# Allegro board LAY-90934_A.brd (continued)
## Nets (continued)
GND: BH1.1 BH2.1 BH3.1 BH4.1 BH5.1 BT1.3 C1.2 C2.2 C3.2 C4.2 C5.2 C6.2 C7.2 C8.2 C9.2 C10.2 C11.2 C12.2 C13.2 C14.2 C15.2 C16.2 C17.2 C18.2 C19.2 C20.2 C21.2 C23.2 C24.2 C25.2 C26.2 C27.1 C28.2 C29.2 C30.2 C31.2 C32.2 C33.2 C34.2 C35.2 C36.2 C37.2 C38.2 C39.2 C40.2 C41.2 C42.2 C43.2 C44.2 C45.2 C46.2 C47.2 C48.2 C49.2 C50.2 C52.2 C54.2 C58.2 C61.2 C63.2 C64.2 C65.2 C66.2 C67.2 C69.2 C70.2 C71.2 C73.2 C74.2 C75.2 C76.2 C77.2 C78.2 C80.2 C81.2 C82.2 C83.2 C84.2 C86.2 C87.1 C88.2 C89.2 C90.2 C91.2 C92.2 C93.2 C94.2 C95.2 C96.2 C97.2 C98.2 C99.2 C100.2 C101.2 C102.2 C103.2 C104.2 C105.2 C106.2 C107.2 C108.2 C109.2 C110.2 C111.2 C112.2 C113.2 C114.2 C115.2 C116.2 C117.2 C118.2 C119.2 C120.2 C121.2 C124.2 C125.1 C127.2 C128.2 C129.2 C130.2 C131.2 C132.2 C133.2 C134.2 C135.2 C136.2 C137.2 C138.2 C139.2 C140.2 C141.2 C142.2 C143.2 C144.2 C145.2 C146.2 C148.2 C150.2 C151.2 C152.2 C153.2 C154.2 C155.2 C156.2 C157.1 C158.2 C159.2 C160.2 C161.2 C162.2 C163.2 C164.2 C167.2 C169.1 C170.2 C171.2 C172.1 C174.1 C175.2 C176.2 C177.2 C178.2 C179.2 C180.2 C182.2 C183.2 C184.2 C185.2 C186.2 C187.1 C188.2 C189.2 C190.2 C191.2 C192.1 C193.2 C194.2 C195.2 C196.2 C197.2 C198.2 C199.2 C200.2 C201.2 C202.2 C203.2 C204.2 C205.2 C206.2 C207.2 C208.2 C209.2 C210.2 C211.2 C212.2 C213.2 C214.2 C215.2 C216.2 C217.2 C218.2 C219.2 C220.2 C221.2 C222.2 C223.2 C224.2 C225.2 C226.2 C227.2 C228.2 C229.2 C230.2 C231.2 C232.2 C233.2 C234.2 C235.2 C236.2 C237.2 C238.2 C239.1 C240.2 C241.1 C242.1 C243.2 C244.2 C245.2 C246.1 C247.2 C248.1 C249.2 C250.2 C251.2 C252.2 C253.2 C255.2 C256.2 C257.2 C258.2 C259.2 C260.2 C261.2 C262.2 C263.2 C264.2 C266.2 C267.2 C268.2 C269.2 C271.2 C272.2 C273.2 C275.2 C276.2 C277.2 C278.2 C279.2 C280.2 C281.2 C282.2 C284.2 C285.2 C286.2 C287.2 C288.2 C289.2 C290.2 C291.2 C292.2 C293.2 C294.2 C295.2 C296.2 C297.2 C298.2 C299.2 C300.2 C301.2 C302.2 C303.2 C304.2 C305.2 C307.2 C308.2 C309.2 C310.2 C311.2 C312.1 C313.2 C314.2 C315.2 C316.2 C317.2 C318.2 D2.3(COM_CATHODE) D6.2(C2) D7.2(C2) D9.2(C2) D10.2(A2) D11.2(C2) D12.2(C2) D13.2(C2) D14.2(A2) D28.C(CATHODE) D29.A GND1.1(TP) GND2.1(TP) GND3.1(PIN1) GND4.1(PIN1) GND5.1(PIN1) GND6.1(PIN1) GND7.1(TP) GND8.1(PIN1) GND9.1(PIN1) GND10.1(PIN1) GND11.1(PIN1) GND12.1(PIN1) GND13.1(PIN1) GND14.1(PIN1) GND15.1(PIN1) GND16.1(PIN1) GND17.1(TP) GND18.1(PIN1) GND19.1(PIN1) GND20.1(PIN1) GND21.1(PIN1) GND22.1(PIN1) GND23.1(PIN1) GND24.1(PIN1) GND25.1(PIN1) GND26.1(TP) GND27.1(TP) GND28.1(PIN1) J1.5 J1.6(B3) J2.4 J3.7 J3.8(B4) J4.6 J4.9 J4.14 J4.20 J4.25 J4.30 J4.34 J4.39 J6.6(VSS) J6.10 J6.11 J6.12 J6.13 J7.3 J7.5 J8.1 J8.7 J8.18 J8.33 J8.39 J8.45 J8.51 J8.57 J8.63 J8.69 J8.75 J10.2 J11.A1 J11.A12 J11.B1 J11.B12 J11.SH1 J11.SH2 J11.SH3 J11.SH4 J12.A1 J12.A12 J12.B1 J12.B12 J12.SH1 J12.SH2 J12.SH3 J12.SH4 J13.A12 J13.B12 J13.SH1 J13.SH2 J13.SH3 J13.SH4 Q1.2(SOURCE) Q3.2(SOURCE) Q4.2(SOURCE) Q5.2(SOURCE) Q6.2(SOURCE) Q8.2(SOURCE) Q9.2(SOURCE) Q10.2(SOURCE) Q11.2(SOURCE) Q12.2(SOURCE) Q13.2(SOURCE) R2.2 R7.2 R8.2 R11.2 R21.2 R26.2 R33.2 R35.2 R36.2 R39.2 R50.2 R53.2 R54.2 R58.2 R59.2 R61.2 R62.2 R66.2 R78.2 R82.1 R83.1 R89.2 R96.2 R111.2 R114.2 R128.2 R150.2 R162.2 R176.2 R199.2 R201.2 R204.2 R207.1 R208.1 R229.2 R230.2 R245.2 R247.2 R254.2 R265.2 R266.2 R269.2 R271.2 R272.2 R273.1 R284.2 R294.2 R298.2 R299.2 R301.2 R302.2 R304.2 R307.2 R308.2 R309.1 R310.2 R311.2 R315.2 R321.2 R334.2 R337.2 R338.2 R340.1 R361.1 R367.1 R377.2 R378.2 R392.2 R394.2 R396.2 R397.2 R399.2 R403.2 R404.2 R411.2 R412.2 R417.2 R421.2 R422.2 R423.2 R424.2 R426.2 R432.2 R439.1 R441.2 R442.2 R452.2 R453.2 R454.2 R455.2 R456.2 R457.2 R463.2 R473.1 R474.2 SW1.1 SW1.2 SW2.1 SW2.2 TP3.1(PIN1) TP12.1(PIN1) TP28.1(PIN1) TP40.1(PIN1) TP75.1(PIN1) TP95.1(PIN1) TP128.1(PIN1) TVS1.1 TVS2.1 TVS3.1 U1.A1 U1.A17 U1.C6 U1.C8 U1.C12 U1.C14 U1.D3 U1.D15 U1.E12 U1.F3 U1.F6 U1.F8 U1.F10 U1.F15 U1.G6 U1.G12 U1.H3 U1.H9 U1.H15 U1.J6 U1.J12 U1.K3 U1.K9 U1.L7 U1.M3 U1.M6 U1.M8 U1.M10 U1.M12 U1.M15 U1.N10 U1.P3 U1.P15 U1.R4(VSS9) U1.R6 U1.R8 U1.R10 U1.R12 U1.R14 U1.U1 U1.U17 U2.A3 U2.A10 U2.AB3 U2.AB5 U2.AB8 U2.AB10 U2.C1 U2.C5 U2.C8 U2.C12 U2.D2 U2.D4 U2.D9 U2.D11 U2.E1 U2.E5 U2.E8 U2.E12 U2.G1 U2.G3 U2.G5 U2.G8 U2.G10 U2.G12 U2.J1 U2.J3 U2.J10 U2.J12 U2.K2 U2.K4 U2.K9 U2.K11 U2.N2 U2.N4 U2.N9 U2.N11 U2.P1 U2.P3 U2.P10 U2.P12 U2.T1 U2.T3 U2.T5 U2.T8 U2.T10 U2.T12 U2.V1 U2.V5 U2.V8 U2.V12 U2.W2 U2.W4 U2.W9 U2.W11 U2.Y1 U2.Y5 U2.Y8(VSS_Y8) U2.Y12 U3.3 U4.5 U4.6 U4.7 U4.8 U5.3 U5.5 U5.6 U5.7 U5.8 U6.C1 U7.2 U8.2 U9.6 U10.6 U11.A2 U11.B1 U12.7(VSS) U12.17 U13.9(VSS) U13.23 U13.24 U13.25 U14.3 U15.25(VSS) U15.26 U15.33 U16.3 U16.17 U17.3 U17.17 U18.4 U18.5 U18.6 U18.7 U18.9 U19.6 U20.4 U20.9 U21.3 U21.17 U22.3 U23.41 U24.6 U25.A6 U25.C4 U25.E7 U25.G5 U25.H10 U25.J5 U25.K8 U25.N2 U25.N5 U25.P4 U25.P6 U26.B1 U27.6 U28.1 U28.5 U28.10 U28.11 U28.13 U28.15 U28.25 U28.35 U28.47 U28.51 U29.6 U30.6 U31.6 U32.10 U33.2 U34.3 U35.41 U36.2(V-) U37.3 U37.8 U38.3 U38.8 U39.3 U39.4 U39.5 U39.6 U39.7 U39.8 U39.25 U39.33 U40.4 U40.13 U41.6 U42.2(VSS) U43.6 U44.6 U45.C3 U45.D3 U45.E3 U46.3 U47.A4 U47.B2 U47.B3 U47.B4 U47.B5 U48.5 U48.17 U49.17 U50.2 U51.B3 U51.D3 U52.B3 U52.D3 U53.3 U54.B1(GND) U55.B1(GND) U56.5 U56.6 U56.7 U56.8 U57.3 U57.5 U57.6 U57.7 U57.8 U58.4 U59.6 U60.10 U60.11 U61.4 U62.4 U63.10 U63.11 U64.3 U64.17 U65.6 U66.3 U67.C1 U68.3 X1.2 X1.4 Y1.2 Y1.4 Y2.2 Y2.4
GND_CHASSIS: C174.2 J9.10 J9.SH1 J9.SH2 R361.2
VBUS1_DET_3V3: R113.1 U1.B3
VBUS_DBG: J11.A4 J11.A9 J11.B4(VBUS4) J11.B9 L13.1 TVS3.2(A2)
VBUS_IN: C141.1 R283.1 TP152.1(PIN1) U39.14 U39.15 U39.16 U39.17 U39.23 U39.35 U45.A1 U45.B1 U45.C1 U45.D1
VBUS_OVLO_TH: R311.1 R313.2 U45.B3
VBUS_USB_DBG: C177.1 C184.1 C189.1 L13.2 U50.1 U50.3
VCC_ANA_1V8: C80.1 C144.1 C145.1 C146.1 L7.2 U1.E6 U1.F12 U1.L12 U1.N8
VCC_FT_1V8: C261.1 C287.1 C290.1 L15.1 U28.12 U28.37 U28.64
VCC_FT_3V3: C31.1 C46.1 C50.1 C52.1 C54.1 C58.1 C64.1 C67.1 C71.1 C188.1 C223.1 C225.1 C229.1 C230.1 C231.1 C235.1 C236.1 C240.1 C258.1 C263.1 C266.1 C272.1 C273.1 C282.1 C284.1 C299.1 C300.1 C311.1 C318.1 D18.A D30.C L16.1 L17.1 R38.1 R60.1 R86.1 R103.1 R112.1 R115.2 R120.2 R124.2 R145.2 R154.1 R172.1 R180.2 R187.1 R195.2 R198.1 R206.1 R219.2 R221.1 R226.2 R252.2 R255.2 R282.1 R296.1 R332.1 R333.1 R413.1 R414.1 R415.1 R464.2 R470.2 TP160.1(TP) U13.21 U14.6 U16.2 U16.15(VDD_I/O) U17.2 U17.15(VDD_I/O) U18.8(VCC) U21.2 U21.15(VDD_I/O) U28.20 U28.31 U28.42 U28.50 U28.56 U42.6 U50.5(VOUT) U60.2(VCCB) U61.8(VCC) U62.8(VCC) U63.3 U64.2 U64.15(VDD_I/O) U65.1 U68.5
VCCO_5V: C304.1 R472.1 U39.21
VDD_1P8: C83.1 C84.1 L9.2 R132.1 R182.1 R184.1 R200.1 R222.1 R234.1 R244.1 R261.1 TP81.1(TP) TP92.1(TP) TP105.1(TP) TP109.1(TP) TP131.1(TP) U23.29
VDD_1V8: C167.1 C237.1 C238.1 C245.1 C255.1 C259.1 C260.1 C286.1 C297.1 C298.1 C308.1 C310.1 D20.A J5.1 R34.1 R91.1 R127.1 R223.1 R233.1 R239.1 R257.1 R258.1 R261.2 R300.1 R325.1 R326.1 R327.1 R328.1 R345.2 R386.1 R387.1 R458.1 R471.1 TP132.1(TP) U20.8 U25.C6 U25.M4 U25.N4 U25.P3 U25.P5 U34.5 U41.1 U43.1 U44.1 U65.11
VDD_3P3: C75.1 C76.1 L6.2 R126.1 R152.1 R161.1 R179.1 R185.1 R192.1 TP57.1(TP) TP69.1(TP) TP70.1(TP) TP76.1(TP) U23.21
VDD_3V3: C4.1 C20.1 C21.1 C29.1 C32.1 C33.1 C34.1 C35.1 C37.1 C40.1 C43.1 C87.2 C113.1 C114.1 C117.1 C120.1 C158.1 C161.1 C224.1 C226.1 C227.1 C228.1 C232.1 C233.1 C234.1 C251.1 C252.1 C256.1 C267.1 C269.1 C288.1 C289.1 C307.1 C309.1 C314.1 C315.1 C316.1 D30.A J3.1 J3.2 L11.1 L14.1 L18.2 R17.1 R20.1 R22.1 R25.1 R27.1 R29.1 R30.1 R32.1 R37.1 R40.1 R42.1 R48.1 R52.1 R63.2 R67.2 R76.1 R81.1 R84.1 R87.1 R88.1 R90.2 R93.1 R94.1 R97.2 R117.1 R149.1 R163.1 R179.2 R196.1 R202.1 R203.1 R249.1 R256.1 R274.1 R276.1 R280.1 R290.1 R291.1 R292.1 R293.1 R306.1 R330.1 R331.1 R373.1 R375.1 R382.1 R402.2 R405.1 R408.1 R430.1 R433.1 R434.1 R467.1 R477.1 R478.2 TP56.1(TP) U3.5 U7.1 U8.5(VIO) U9.14(VDD) U10.14(VDD) U11.A1(VCC) U15.27 U15.31 U23.32 U25.E6 U25.F5 U25.J10 U25.K9 U27.14(VDD) U29.14(VDD) U30.14(VDD) U31.14(VDD) U40.15 U41.11(VREF_B) U43.11(VCCB) U44.11(VCCB) U48.3(VDD) U49.3(VDD) U53.5 U59.14(VDD) U60.3 U63.2(VCCB)
VDD_5V: C5.1 C6.1 C7.1 C15.1 C18.1 C127.1 C192.2 C200.1 C312.2 J2.1 R289.1 R479.1 TP185.1(PIN1) U8.3 U36.5 U48.12 U49.12 U58.7(VOUT) U67.A2 U67.B2
VDD_ANA_0P8: C92.1 R251.1 R459.1 TP113.1(TP) TP121.1(TP) U23.1
VDD_ANA_0V8: C130.1 C131.1 C132.1 C133.1 R251.2 R450.1 TP126.1(TP) U1.C4 U1.F13 U1.M13
VDD_ANA_1V8: L7.1 R183.1 R222.2 TP80.1(TP)
VDD_COIN_3V: BT1.1 BT1.2(POS2) R46.2 R47.1
VDD_RTC_3V3: C23.1 C24.1 R19.2 U12.15
VDD_SNVS_0V8: C102.1 U1.C10
VDD_SOC: C104.1 C105.1 C106.1 C107.1 C108.1 C109.1 C110.1 C111.1 R241.2 R242.2 R461.1 R469.1 TP117.1(TP) U1.G7 U1.G9 U1.G11 U1.H7 U1.H11 U1.K7 U1.K11
VDD_SOC_0V85: C81.1 C82.1 L8.2 R235.1 R240.1 R460.1 TP102.1(TP) TP116.1(TP) U24.3 U24.11
VDD_SOC_SW: R214.2 R215.2 TP85.1(PIN1) U24.5
VDD_USB_3V3: C155.1 R165.1 R192.2 TP68.1(TP) U1.E8
VDD_VBAT_3V: C30.1 R47.2 U12.16
VEN_SPI_CS/1V8: J8.64 R344.1 R345.1
VINT: C89.1 U23.36
ADC0: J5.2 J5.4 R98.1
ADC1: J5.6 J5.8(B4) R65.1
ADC_GND: J5.7 R33.1
ADC_HIGH: J5.3 R36.1 R37.2
ADC_IN0: C45.1 R98.2 U1.B8
ADC_IN1: C44.1 R65.2 U1.A8
ADC_LOW: J5.5 R34.2 R35.1
AUD_NMUTE: R139.2 R308.1 U40.11
BT_MODE0: R431.2 U63.6
BT_MODE1: R429.2 U63.7
BT_MODE2: R428.2 U63.8
BT_MODE3: R427.2 U63.9
BUF_POR: R118.1 R256.2 U34.4(Y)
BYPASS1: C187.2 U48.4
CAN1_RX: R15.1 TP4.1(TP) U10.1
CAN1_TX: R16.1 TP5.1(TP) U10.8
CAN_H: C27.2 D2.1 J2.2 L3.2 L4.3 R43.2
CAN_L: C28.1 D2.2 J2.3 L3.3 L4.2 R44.1
CAN_RX: R15.2 U8.4
CAN_STBY: R76.2 U8.8 U10.4
CAN_TX: R16.2 U8.1
CANH: L3.1 L4.4 U8.7
CANL: L3.4 L4.1 U8.6
CLKIN1: R54.1 TP20.1(PIN1) U1.A6
CLKIN2: R53.1 TP19.1(PIN1) U1.B6
CLKO01: R224.2 TP104.1(PIN1)
CON_JTAG_NRST: D22.C D23.C J7.10(B5) R259.2
DAC_BCLK: R278.2 U40.9
DAC_DAT: R297.2 U40.7
DAC_LRCLK: R287.2 U40.8
DAC_MCLK: R285.2 U40.10
DBG_ACC: TP154.1(PIN1) U48.9
DCDC_5V: C100.1 C103.1 C124.1 C142.1 C143.1 C154.1 C156.1 C168.1 C170.1 C173.2 C194.1 C317.1 R232.1 R260.1 R277.1 R323.1 R341.1 R365.2 TP139.1(TP) TP145.1(TP) TP188.1(PIN1) U32.8 U32.11(VIN2) U33.1 U33.3 U39.28(VOUT) U47.D2 U47.D3 U47.E2 U47.E3 U47.F2 U47.F3 U47.G2 U47.G3 U58.1 U58.3 U58.8
DMIC_PDM_CLK: TP1.1(TP) U10.9 U66.2
DMIC_PDM_DATA0: TP161.1(TP) U10.16 U53.4(Y)
DMIC_PDM_DATA1: TP2.1(TP) U3.4(Y) U10.3
DRAM_CA0_A: TP36.1(PIN1) U1.F1 U2.H2
DRAM_CA1_A: U1.E2 U2.J2
DRAM_CA2_A: U1.D2 U2.H9
DRAM_CA3_A: U1.C1 U2.H10
DRAM_CA4_A: U1.B2 U2.H11
DRAM_CA5_A: U1.A2 U2.J11
DRAM_CK_C_A: R205.2 U1.B1 U2.J9
DRAM_CK_T_A: R205.1 U1.C2 U2.J8
DRAM_CKE0_A: R207.2 U1.G1 U2.J4
DRAM_CKE1_A: R208.2 U1.F2 U2.J5
DRAM_DATA0_A: TP60.1(PIN1) U1.L2 U2.F4
DRAM_DATA1_A: TP54.1(PIN1) U1.L1 U2.E4
DRAM_DATA2_A: TP51.1(PIN1) U1.K2 U2.C4
DRAM_DATA3_A: TP49.1(PIN1) U1.K1 U2.B4
DRAM_DATA4_A: TP47.1(PIN1) U1.J1 U2.B2
DRAM_DATA5_A: TP45.1(PIN1) U1.H2 U2.C2
DRAM_DATA6_A: TP39.1(PIN1) U1.H1 U2.E2
DRAM_DATA7_A: TP43.1(PIN1) U1.G2 U2.F2
DRAM_DATA8_A: TP78.1(PIN1) U1.T2 U2.E11
DRAM_DATA9_A: TP79.1(PIN1) U1.U2 U2.F11
DRAM_DATA10_A: TP77.1(PIN1) U1.T1 U2.C11
DRAM_DATA11_A: TP73.1(PIN1) U1.R2 U2.B11
DRAM_DATA12_A: TP67.1(PIN1) U1.N1 U2.C9
DRAM_DATA13_A: TP72.1(PIN1) U1.N2 U2.B9
DRAM_DATA14_A: TP65.1(PIN1) U1.M2 U2.E9
DRAM_DATA15_A: TP64.1(PIN1) U1.M1 U2.F9
DRAM_DMI0_A: TP48.1(PIN1) U1.J2 U2.C3
DRAM_DMI1_A: U1.R1 U2.C10
DRAM_NCS0_A: TP35.1(PIN1) U1.D1 U2.H4
DRAM_NCS1_A: U1.E1 U2.H3
DRAM_NRESET: R102.1 R201.1 U1.F4 U2.T11
DRAM_SDQS0_C_A: U1.K4 U2.E3
DRAM_SDQS0_T_A: U1.M4 U2.D3
DRAM_SDQS1_C_A: U1.P2 U2.E10
DRAM_SDQS1_T_A: U1.P1 U2.D10
DRAM_ZN: R204.1 U1.H4
DRAM_ZQ0: R209.2 U2.A5
DRAM_ZQ1: R211.1 U2.A8
EE_CLK: R332.2 R342.1 TP158.1(PIN1) U42.4
EE_CS: R333.2 R343.1 TP159.1(PIN1) U42.5
EE_DATA: R281.2 R295.1 TP147.1(PIN1) U42.3
EMMC_VDDIM: C244.1 C247.1 U25.C2
EN_SNK: R370.2 U47.F1
EN_SRC: R369.2 U47.G1
ENET1_MDC: R267.1 TP143.1(PIN1) U1.T8
ENET1_MDIO: R263.1 R471.2 TP140.1(PIN1) U1.U7
ENET1_NINT: R249.2 U1.D14 U35.31
ENET1_NRST: R95.2 R274.2 TP144.1(PIN1) U35.12
ENET1_RD0: R446.2 R455.1 TP83.1(PIN1) U1.U5 U35.25
ENET1_RD1: R445.2 R454.1 U1.T6 U35.24
ENET1_RD2: R444.2 R453.1 U1.U6 U35.23
ENET1_RD3: R443.2 R452.1 U1.T7 U35.22
ENET1_RX_CTL: R456.1 TP89.1(PIN1) U1.T5 U35.26
ENET1_RXC: C262.1 R447.2 R457.1 TP84.1(PIN1) U1.U4 U35.27
ENET1_TD0: TP137.1(PIN1) U1.U9 U35.18
ENET1_TD1: U1.R9 U35.17
ENET1_TD2: U1.U10 U35.16
ENET1_TD3: U1.T10 U35.15
ENET1_TX_CTL: TP134.1(PIN1) U1.T9 U35.19
ENET1_TXC: TP133.1(PIN1) U1.U8 U35.20
ETH1_10/100M_LINK/ACTIVE: J9.13 R305.1
ETH1_1000M_LINK/ACTIVE: J9.11 R303.1 R304.1
ETH1_AVDD1V0: C285.1 C291.1 C295.1 C296.1 R468.2 U35.3 U35.8 U35.38
ETH1_AVDD3V3: C294.1 C301.1 L11.2 U35.11 U35.40
ETH1_CLK125_OUT: TP138.1(PIN1) U35.35
ETH1_CT: C148.1 J9.1
ETH1_DVDD1V0: C276.1 C277.1 R462.2 U35.21
ETH1_DVDD3V3: C280.1 C281.1 L14.2 R246.1 R253.1 R303.2 U35.29
ETH1_LED0/CFG_EXT: R246.2 R247.1 R305.2 U35.32
ETH1_LED1/CFGLDO0: C94.1 J9.14 R245.1 U35.33
ETH1_LED2/CFGLDO1: C95.1 J9.12 R253.2 R254.1 U35.34
ETH1_TRX0_N: J9.3 U35.2 U37.2 U37.9
ETH1_TRX0_P: J9.2 U35.1 U37.1 U37.10(NC4)
ETH1_TRX1_N: J9.5 U35.5 U37.5 U37.6
ETH1_TRX1_P: J9.4 U35.4 U37.4 U37.7
ETH1_TRX2_N: J9.7 U35.7 U38.2 U38.9
ETH1_TRX2_P: J9.6 U35.6 U38.1 U38.10(NC4)
ETH1_TRX3_N: J9.9(TRD4-) U35.10 U38.5 U38.6
ETH1_TRX3_P: J9.8 U35.9 U38.4 U38.7
ETH1_VDD1V0: C271.1 C275.1 R462.1 R468.1 TP135.1(TP) U35.30
ETH1_VDDIO: C278.1 C279.1 R443.1 R444.1 R445.1 R446.1 R447.1 R458.2 U35.28
ETH1_XTALI: C112.1 R264.2 U35.36 Y2.3
ETH1_XTALO: C121.1 R264.1 U35.37(XTAL_OUT/ EXT_CLK) Y2.1
EXP3V3_EN: R5.1 R70.2
EXP5V_EN: R1.1 R141.2
EXP_3V3: C19.1 C26.1 L2.1 U6.A1 U6.B1(VOUT2)
EXP_5V: C2.1 C3.1 L1.2 U67.A1 U67.B1(VOUT2)
EXP_GPIO_IO08: J4.24 U9.3
EXP_GPIO_IO09: J4.21 U9.9
EXP_GPIO_IO10: J4.19 U9.12
EXP_GPIO_IO11: J4.23 U9.16
EXP_NIRQ: R135.1 R224.1 U1.T4
EXP_SEL: R61.1 R69.2 U9.15
EXT1_PWREN: R101.2 R279.1 R480.2
FRS_EN: U47.B6 U48.1
FSC_CTRL_H1: R215.1 U61.7
FSC_CTRL_H2: R435.1 U61.5
FT_BMODE_DIR: R432.1 U13.14 U63.4 U63.5
FT_BOOT_MODE0: R431.1 U13.1
FT_BOOT_MODE1: R429.1 U13.2
FT_BOOT_MODE2: R428.1 U13.3
FT_BOOT_MODE3: R427.1 U13.4
FT_CTRL_H1: R413.2 U13.5 U61.1
FT_CTRL_H2: R414.2 U13.6 U61.3
FT_CTRL_H3: TP18.1(PIN1) U13.7
FT_EECLK: R342.2 U28.62
FT_EECS: R343.2 U28.63
FT_EEDATA: R295.2 U28.61
FT_EXP_SCL: R45.2 U13.19
FT_EXP_SDA: R51.2 U13.20
FT_IO_NINT1: R64.1 U28.30
FT_NPWREN: TP136.1(PIN1) U28.60
FT_NSUSPEND: TP99.1(PIN1) U28.36
FT_ONOFF: R397.1 U13.12 U62.3
FT_OSCI: C128.1 U28.2 X1.1
FT_OSCO: C134.1 U28.3 X1.3
FT_POR_B: R417.1 U13.10 U62.6
FT_RC_SEL: R77.1 U13.13
FT_SCL: R45.1 R155.1 R159.2 R164.2 R227.2 R255.1 R451.2 TP37.1(TP) U28.26
FT_SD_CD: U13.16 U68.2
FT_SD_CD_EN: R203.2 U22.1 U68.4(Y)
FT_SD_PWR_EN: R202.2 R216.1 U61.2
FT_SD_PWREN: R415.2 U13.15 U61.6
FT_SDA: R51.1 R156.1 R160.2 R170.2 R228.2 R252.1 R449.2 TP38.1(TP) U28.27 U28.28
FT_SYS_NRST: R399.1 U13.11 U62.1
FT_TEMP_NINT: R154.2 TP46.1(PIN1) U18.3
FT_TST0: R178.1 U28.21
FT_TST1: R194.1 U28.22
FT_TST2: R212.1 U28.23
FT_TST3: R225.1 U28.24
FT_USB_DN: U28.7 U54.C1
FT_USB_DP: U28.8 U54.C2
FTA_TCK: U28.16 U65.2
FTA_TDI: U28.17 U65.3
FTA_TDO: U28.18 U65.5
FTA_TMS: U28.19 U65.4
FTC_RXD: D16.C(CATHODE) R409.1 U28.39
FTC_TXD: D17.C(CATHODE) R410.1 U28.38
GPIO_IO00: J4.27 R49.2 U1.B16
GPIO_IO01: J4.28 R41.2 U1.B17
GPIO_IO02: J4.3 R23.2 U1.C16
GPIO_IO03: J4.5 R24.2 U1.C17
GPIO_IO04: J4.7 R395.1 U1.D16
GPIO_IO05: J4.29 U1.D17
GPIO_IO06: J4.31 U1.E16
GPIO_IO07: J4.26 U1.E17
GPIO_IO08: U1.K14 U9.5
GPIO_IO09: U1.F16 U9.7
GPIO_IO10: U1.F17 U9.10
GPIO_IO11: U1.G16 U9.2
GPIO_IO12: J4.32 R391.1 U1.F14
GPIO_IO13: J4.33 R393.1 U1.G17
GPIO_IO14: J4.8 U1.H16
GPIO_IO15: J4.10 U1.H17
GPIO_IO16: U1.J16 U59.16
GPIO_IO17: J4.11 U1.K15
GPIO_IO18: J4.12 U1.M14 U59.1
GPIO_IO19: J4.35 U1.J17 U59.4
GPIO_IO20: J4.38 U1.K16
GPIO_IO21: J4.40 U1.K17
HP_J_L: C171.1 J10.4 R335.2 TP162.1(TP) TVS2.2(A2)
HP_J_R: C172.2 J10.3 R336.2 TP163.1(TP) TVS1.2(A2)
I2C1_SCL: R94.2 R122.1 R292.2 R366.2 R419.1 TP168.1(TP) U41.8
I2C1_SCL_1V8: R327.2 R347.2 U41.4
I2C1_SDA: R93.2 R130.1 R293.2 R363.2 R420.1 TP164.1(TP) U41.7
I2C1_SDA_1V8: R328.2 R348.2 U41.5
I2C2_SCL: R87.2 R121.1 R169.1 TP42.1(TP) U1.A11
I2C2_SDA: R88.2 R129.1 R168.1 TP41.1(TP) U1.B11
I2C3_SCL: R40.2 R41.1
I2C3_SDA: R48.2 R49.1
I2C4_SCL: R24.1 R25.2 R28.1
I2C4_SDA: R22.2 R23.1 R31.1
I2C/I3C1_SCL: R406.2 R419.2 U1.A12
I2C/I3C1_SDA: R407.2 R420.2 U1.B12
I3C1_SCL: R405.2 R406.1 TP17.1(TP) U11.B2
I3C1_SDA: R407.1 R408.2 TP16.1(TP) U11.C2
I.MX_SPI_CLK: R351.2 U43.3
I.MX_SPI_CS: R324.2 U43.2
I.MX_SPI_MISO: R352.2 U43.4
I.MX_SPI_MOSI: R353.2 U43.5
ILIM_5V_VBUS: TP171.1(PIN1) U48.6
IOEXP_IO24: J4.18(B9) R144.2
IOEXP_IO25: J4.22 R143.2
IOEXP_IO27: J4.13 R131.2
JTAG_TCK: R229.1 TP88.1(PIN1) U1.U3 U27.2
JTAG_TDI: TP96.1(PIN1) U1.P8 U27.5
JTAG_TDO: TP86.1(PIN1) U1.T3 U27.10
JTAG_TMS: TP87.1(PIN1) U1.P6 U27.7
JTG_TCK: J7.4 U27.1 U65.10
JTG_TDI: J7.8 R258.2 U27.4 U65.9
JTG_TDO: J7.6 U27.11 U65.7
JTG_TMS: J7.2 R257.2 U27.8 U65.8(YB3)
LD_I2C_SCL: R368.1 U47.B1
LD_I2C_SDA: R364.1 R475.1 U47.C1
LD_NFLT: R329.1 R330.2 U48.11
LD_NINT: R329.2 U47.D1
LED_B: Q11.3 R388.2
LED_G: Q13.3 R390.2
LED_R: Q12.3 R389.2
LINE_L: C166.1 R335.1 U40.1
LINE_R: C165.1 R336.1 U40.16
LINEVDD: C305.1 L18.1 U40.6
LPD4_VDD1: C201.1 C202.1 C203.1 C204.1 C205.1 C209.1 R181.1 R234.2 TP91.1(TP) U2.F1 U2.F12 U2.G4 U2.G9 U2.T4 U2.T9 U2.U1 U2.U12
LPD4_VDD2: C136.1 C137.1 C138.1 C139.1 C140.1 C151.1 C152.1 C153.1 C206.1 C207.1 C208.1 C210.1 C211.1 C212.1 C213.1 C214.1 C215.1 C216.1 C217.1 C218.1 C219.1 C220.1 C221.1 C222.1 R148.1 R166.1 R174.2 R209.1 R210.1 R211.2 TP53.1(TP) U1.F5 U1.H5 U1.K5 U1.M5 U1.N6 U1.P4 U2.A4 U2.A9 U2.AA3 U2.AA5 U2.AA8 U2.AA10 U2.AB4 U2.AB9 U2.B3 U2.B5 U2.B8 U2.B10 U2.D1 U2.D5 U2.D8 U2.D12 U2.F3 U2.F5 U2.F8 U2.F10 U2.H1 U2.H5 U2.H8 U2.H12 U2.K1 U2.K3 U2.K10 U2.K12 U2.N1 U2.N3 U2.N10 U2.N12 U2.R1 U2.R5 U2.R8 U2.R12 U2.U3 U2.U5 U2.U8 U2.U10 U2.W1 U2.W5 U2.W8 U2.W12
LPD4_VDD2_1V1: C73.1 C74.1 L5.2 R167.1 R175.1 TP52.1(TP) TP74.1(TP) U19.3 U19.11 U23.10
LPD4_VDD2_SW: R435.2 R437.2 TP71.1(PIN1) U19.5
LX1: L5.1 U23.8 U23.9
LX2: L8.1 U23.4 U23.5
LX3: L9.1 U23.27 U23.28
LX4: L6.1 U23.22 U23.23
M1_SCL: R451.1 U64.4
M1_SDA: R449.1 U64.5
M2_32K_IN: Q9.1 R146.1 R157.1
M2_ALERT_B: R326.2 R346.2 U41.3
M2_ALT_B: J8.62 R346.1
M2_I2C_SCL: J8.60 R347.1
M2_I2C_SDA: J8.58 R348.1
M2_LED1#: D27.C(CATHODE) J8.6
M2_LED2#: D26.C(CATHODE) J8.16
M2_LS_OE: R314.1 R315.1 U41.12 U43.12
M2_NALERT: R119.2 R291.2 U41.9
M2_NDIS1: J8.56 R71.2 R286.1
M2_NDIS2: J8.54(W\_\D\I\S\A\B\L\E\2\) R72.2 R310.1 R316.2
M2_PCM_CLK: J8.8 R358.2
M2_PCM_IN: J8.12 R356.2
M2_PCM_OUT: J8.14 R355.2
M2_PCM_SYNC: J8.10 R357.2
M2_PWRON: R272.1 R276.2 R279.2 R286.2 U32.5
M2_SAI1_RXD0: U31.11 U44.9
M2_SAI1_TXC: U31.4 U44.7
M2_SAI1_TXD0: U31.8 U44.10
M2_SAI1_TXFS: U31.1 U44.8
M2_SCL: R159.1 U16.4
M2_SD_CLK: J8.9 TP183.1(PIN1) U29.16
M2_SD_CMD: J8.11 R387.2 TP181.1(PIN1) U29.3
M2_SD_DATA0: J8.13 R386.2 TP180.1(PIN1) U30.9
M2_SD_DATA1: J8.15 U30.12
M2_SD_DATA2: J8.17 U30.16
M2_SD_DATA3: J8.19 U30.3
M2_SD_NWAKE: J8.21 R325.2 TP179.1(PIN1) U41.2
M2_SDA: R160.1 U16.5
M2_UART_NWAKE: J8.20 R140.2 R354.2
M2_USB_DN: J8.5 TP184.1(PIN1)
M2_USB_DP: J8.3 TP182.1(PIN1)
M3_SCL: R164.1 U17.4
M3_SDA: R170.1 U17.5
M4_SCL: R227.1 U21.4
M4_SDA: R228.1 U21.5
MIC/CAN_SEL: R74.2 R89.1 SW4.5 U10.15
MX_POR_B: C36.1 R55.2 R56.2 TP21.1(PIN1) U1.B7
NVCC_1V8: C115.1 C116.1 R197.1 R244.2 TP108.1(TP) U1.L6 U1.L9 U1.L11
NVCC_3V3: C118.1 C119.1 R125.1 R185.2 TP58.1(TP) U1.H13 U1.K13
NVCC_BBSM_1P8: C90.1 R190.1 R243.1 R448.1 TP111.1(TP) TP119.1(TP) U23.38
NVCC_BBSM_1V8: C101.1 J1.1 J1.2 R6.1 R9.1 R56.1 R57.1 R92.1 R243.2 R440.1 TP118.1(TP) U1.E10
NVCC_SD: C91.1 C257.1 R213.1 R250.1 TP112.1(TP) TP120.1(TP) U23.39
NVCC_SD2: C77.1 C129.1 R151.1 R173.1 R218.1 R220.1 R250.2 R312.1 TP127.1(TP) U1.N12 U22.5
ODT_CA_A: R210.2 U2.G2
ONOFF: C9.1 R10.2 R92.2 R416.2 TP27.1(PIN1) U1.D10
PD_BYPASS: C169.2 U49.4
PD_DBG_ACC: TP170.1(PIN1) U49.9
PD_EN_SINK: R339.1 U49.2
PD_EN_SRC: TP165.1(PIN1) U49.16
PD_FRS_EN: TP157.1(PIN1) U49.1
PD_ILIM_5V_VBUS: TP156.1(PIN1) U49.6
PD_LD_NFLT: R376.1 U49.11
PD_USB_CC1: U49.13 U52.A2
PD_USB_CC2: U49.14 U52.B2 U52.C1 U52.C2
PD_VBUS_PG: Q10.1 R374.2 TP153.1(PIN1) U45.A2
PDM_CLK: U1.A16 U10.7
PDM_CLK_1V8: R3.1 R4.1 R371.1 R372.1 U66.4(Y)
PDM_D0: R379.2 R384.2 U53.2
PDM_D1: R12.2 R13.2 U3.2
PDM_DATA0: U1.A10 U10.2
PDM_DATA1: U1.B10 U10.5
PERST: J8.52 R480.1
PMIC_32K_OUT: R157.2 U23.14
PMIC_NINT: R116.2 R117.2 U23.19
PMIC_ON_REQ: Q5.1 R57.2 R58.1 R191.1 R476.1 TP22.1(PIN1) U1.A7
PMIC_STBY_REQ: Q6.1 R59.1 R237.1 TP23.1(PIN1) U1.C9
POR_B: D23.A Q4.1 R55.1 R398.2 U23.11 U34.2
QSPIA_DATA0: TP62.1(TP) U20.5 U30.8
QSPIA_DATA1: U20.2 U30.11
QSPIA_DATA2: U20.3(W\P\/SIO2) U30.1
QSPIA_DATA3: U20.7 U30.4
QSPIA_NSS0: R233.2 TP98.1(TP) U20.1 U29.4
QSPIA_SCLK: TP61.1(TP) U20.6 U29.1
RC_BT_MODE0: R109.1 R421.1 SW3.7 U63.15
RC_BT_MODE1: R108.1 R422.1 SW3.5 U63.14
RC_BT_MODE2: R107.1 R423.1 SW3.3 U63.13
RC_BT_MODE3: R106.1 R424.1 SW3.1 U63.12
RC_NSEL: D5.C(CATHODE) Q1.3 R103.2 U63.1 U63.16 U65.12
RC_SEL: Q1.1 R425.2 R426.1 U14.4(Y)
REG_FEQ: R309.2 U39.29
REG_FT_1V8: C264.1 C268.1 L15.2 TP115.1(TP) U28.49(VREGOUT)
REG_MODE: R472.2 R473.2 U39.2
REG_ST: C125.2 U39.24
RTC_CLKO: R146.2 TP25.1(PIN1) U12.6
RTC_NINTA: R20.2 R138.2 TP9.1(PIN1) U12.13
RTC_SCL: R80.2 R81.2 U12.2
RTC_SDA: R84.2 R85.2 U12.5
S1_LPD4_VDD2: R134.1 R174.1 R175.2 TP63.1(TP) U19.10(VOUT)
S1_VDD_SOC_0V8: R240.2 R241.1 R466.1 TP106.1(TP) U24.10(VOUT)
SAI1_DAC_MCLK: R285.1 TP148.1(PIN1) U31.12
SAI1_DAC_TXC: R278.1 TP146.1(PIN1) U31.3
SAI1_DAC_TXD: R297.1 TP150.1(PIN1) U31.9
SAI1_DAC_TXFS: R287.1 TP149.1(PIN1) U31.16
SAI1_EN_B: R123.2 R465.1
SAI1_RXD0: U1.B14 U31.10
SAI1_SEL: R66.1 R73.2 SW4.3 U31.15
SAI1_TXC: U1.B15 U31.5
SAI1_TXD0: R106.2 TP33.1(TP) U1.A15 U31.7
SAI1_TXFS: R107.2 TP34.1(TP) U1.A14 U31.2
SAI3_EN_B: R52.2 R68.2 U59.13
SAI3_TX/RX_SEL: R50.1 R99.2 U59.15
SAI3_TX_SYNC: R108.2 TP32.1(TP) U1.D12 U59.3
SAI3_TXBCLK/RXBCLK: J4.36 U59.2
SAI3_TXSYNC/RXSYNC: J4.37 U59.5
SD1_CLK: TP110.1(PIN1) U1.U11 U25.M6
SD1_CMD: R239.2 TP107.1(PIN1) U1.T11 U25.M5
SD1_DATA0: R223.2 TP90.1(PIN1) U1.T13 U25.A3
SD1_DATA1: U1.T14 U25.A4
SD1_DATA2: U1.T15 U25.A5
SD1_DATA3: U1.U13 U25.B2
SD1_DATA4: U1.T12 U25.B3
SD1_DATA5: U1.U14 U25.B4
SD1_DATA6: U1.U15 U25.B5
SD1_DATA7: U1.U16 U25.B6
SD1_STROBE: TP93.1(PIN1) U1.U12 U25.H5
SD2_CLK: R171.1 TP50.1(PIN1) U1.M16
SD2_CMD: R151.2 R153.1 TP44.1(PIN1) U1.M17
SD2_DATA0: R173.2 R177.1 TP55.1(PIN1) U1.N17
SD2_DATA1: R186.1 U1.N16
SD2_DATA2: R133.1 U1.L17
SD2_DATA3: R147.1 U1.L16
SD2_NCD: R217.1 R218.2 U1.P12 U22.4(Y)
SD2_NDET: D14.1 J6.9 R196.2 R217.2 TP82.1(TP) U22.2
SD2_NRST: R236.1 R312.2 U1.P10
SD2_VSEL: U1.P14 U23.35
SD3_CLK: U1.T16 U29.2
SD3_CMD: U1.T17 U29.5
SD3_DATA0: U1.R16 U30.7
SD3_DATA1: U1.R17 U30.10
SD3_DATA2: U1.P16 U30.2
SD3_DATA3: U1.P17 U30.5
SD3_NRST: J8.23 R110.2 R111.1 TP178.1(PIN1)
SD3_NWAKE: R142.2 R290.2 U41.10
SD3_QSPI_SEL: R62.1 R75.2 R248.1 SW4.1 U29.15 U30.15
SD_CLK: D11.1 J6.5 R171.2
SD_CMD: D9.1 J6.3 R153.2
SD_DATA0: D12.1 J6.7 R177.2
SD_DATA1: D13.1 J6.8 R186.2
SD_DATA2: D6.1 J6.1 R133.2
SD_DATA3: D7.1 J6.2 R147.2
SPI3_CLK: U9.1 U43.9
SPI3_CS0: U9.4 U43.10
SPI3_MISO: U9.8 U43.8
SPI3_MOSI: U9.11 U43.7
STAR_I2C_SCL: J3.3 J3.4 R28.2
STAR_I2C_SDA: J3.5 J3.6 R31.2
SUSCLK: J8.50 R349.1
SUSCLK_32K: Q9.3 R349.2 R350.2
SYS_NRST: C17.1 D22.A R14.2 R189.1 R418.2 TP66.1(TP)
TAMPER0: J1.3 R8.1 R9.2 U1.D6
TAMPER1: J1.4 R6.2 R7.1 U1.D8
TCPC1_NINT: R136.1 R331.2 U48.10
TCPC_NINT: R137.2 R373.2 TP169.1(PIN1) U49.10
TEMP_NINT: R42.2 TP14.1(PIN1) U11.C1
UART1_RXD: R401.2 TP186.1(TP) U1.B13
UART1_TXD: R109.2 R400.2 TP29.1(TP) TP187.1(TP) U1.A13
UART5/JTAG_SEL: R96.1 R248.2 SW4.7 U27.15
UART5_CTSI: J8.34 U27.16
UART5_RTSO: J8.36 U27.9
UART5_RXD: J8.22 U27.3
UART5_TXD: J8.32 U27.12
USB1_CC1: U48.13 U51.A2
USB1_CC2: U48.14 U51.B2 U51.C1 U51.C2
USB1_DN: U1.A4 U55.C1
USB1_DP: U1.B4 U55.C2
USB1_ID: R91.2 TP26.1(PIN1) U1.D4
USB1_VBUS_3V3: R113.2 R280.2 U36.1
USB1_VBUS_IN: C181.2 TP167.1(PIN1) U47.C6 U47.D6 U47.E6 U47.F6 U47.G6
USB_CC1_PD: J13.A5 R381.1 TP175.1(PIN1)
USB_CC1_PD_OVP: R383.2 U52.A1
USB_CC2_PD: J13.B5 R380.1 TP176.1(PIN1)
USB_CC2_PD_OVP: R385.2 U52.B1
USB_DBG_CC1: J11.A5 R377.1
USB_DBG_CC2: J11.B5 R378.1
USB_DBG_DN: J11.A7 J11.B7 U54.A1
USB_DBG_DP: J11.A6 J11.B6 U54.A2
USB_I2C_SCL: R80.1 R359.2 R366.1 R368.2 U49.8
USB_I2C_SDA: R85.1 R362.2 R363.1 R364.2 U49.7
USB_PD_VBUS: F1.1 J13.A9 J13.B9(VBUS2)
USB_PD_VBUS_F: C193.1 D25.A F1.2 R313.1 R319.1 U45.B2 U45.C2 U45.D2 U45.E1 U45.E2 U49.15
USBC_CC1: J12.A5 TP173.1(PIN1) U51.A1
USBC_CC2: J12.B5 TP174.1(PIN1) U51.B1
USBC_DN: J12.A7 J12.B7 U55.A1
USBC_DP: J12.A6 J12.B6 U55.A2
USBC_EN_SNK1: R370.1 U48.2
USBC_EN_SRC1: R369.1 U48.16
USBC_I2C_SCL: R359.1 U48.8
USBC_I2C_SDA: R362.1 U48.7
USBC_VBUS: F2.1 J12.A4 J12.A9 J12.B4(VBUS4) J12.B9
USBC_VBUS_F: C150.1 D24.A F2.2 R288.1 R294.1 U47.C2 U47.C3 U47.C4 U47.C5 U47.D4 U47.D5 U47.E4 U47.E5 U47.F4 U47.F5 U47.G4 U47.G5 U48.15
VBBS: C25.1 U12.14
VEN_SPI_CLK: J8.42 R351.1
VEN_SPI_CS: R324.1 R344.2
VEN_SPI_MISO: J8.40 R352.1
VEN_SPI_MOSI: J8.38 R353.1
VEXP_3V3: J4.1 J4.17 L2.2
VEXP_5V: J4.2 J4.4 L1.1
VEXT_3V3: C16.1 C98.1 C99.1 C122.1 C123.2 C178.1 C179.1 C185.1 C186.1 C190.1 C191.1 D1.2 J8.2 J8.4 J8.72 J8.74 L10.2 R268.1 R314.2 R318.2 R322.2 R350.1 R354.1 TP141.1(TP) U6.A2 U6.B2 U32.2
VLDO1_3V3: C182.1 U47.A5(VLDO)
VLDO_3V3: C175.1 C176.1 C195.1 C313.1 D3.A R19.1 R79.1 R320.1 R374.1 U46.1(OUT) U47.A1 U51.A3(VSYS) U52.A3(VSYS)
VLS_3V3: C65.1 C66.1 C243.1 C249.1 D18.C D19.C R214.1 R436.1 R437.1 R438.1 TP124.1(TP) U19.4 U24.4
VMIC_1V8: C1.1 C8.1 C10.1 C11.1 C12.1 C13.1 C14.1 C22.1 C196.1 C197.1 C198.1 C199.1 R18.1 TP6.1(TP) U4.3 U4.4(VDD) U5.4(VDD) U7.5(OUT) U56.3 U56.4(VDD) U57.4(VDD) U66.5
VSD2_3V3: C61.1 C86.1 D10.1 J6.4 R238.2 TP94.1(TP) U26.A1(VOUT)
VSD_3V3: C88.1 C93.1 R238.1 U23.33 U26.A2
VSYS: C254.2 R481.2 U23.37
VSYS_5V: C239.2 C241.2 C242.2 C246.2 C248.2 C250.1 C253.1 R231.1 R260.2 R481.1 TP130.1(TP) U23.2 U23.6 U23.7 U23.24 U23.25 U23.26 U23.40
VSYS_5V_COMP: C160.1 R317.1 U39.30
VSYS_5V_FB: C168.2 R341.2 R474.1 U39.31
VSYS_EN: R283.2 U39.26
VTREF: J7.1 R300.2
WDOG_B: Q3.1 R163.2 R188.1 TP59.1(TP) U1.H14
XIN_32K: C70.1 QZ2.2 R193.1 U23.16
XOUT_32K: C69.1 QZ2.1 R193.2 U23.17(XTAL_OUT)
XTALI_24M: C42.1 R105.1 TP31.1(PIN1) U1.A9 Y1.1
XTALI_32K: C48.1 QZ1.2 R104.1 TP30.1(PIN1) U1.A5
XTALO_24M: C41.1 R105.2 U1.B9 Y1.3
XTALO_32K: C47.1 QZ1.1 R104.2 U1.B5
N117383326: R281.1 R296.2 U42.1
N117385728: C274.1 R460.2 U64.11
N117385807: C274.2 R461.2 U64.12
N117385857: C283.1 R466.2 U64.13
N117385909: C283.2 R469.2 U64.14
N117385984: C265.1 R448.2 U64.8
N117385990: R441.1 U64.6
N117386025: R463.1 R464.1 U64.1
N117386063: C265.2 R440.2 U64.7
N117386111: R470.1 U64.16
N117386128: C270.1 R459.2 U64.10
N117386168: C270.2 R450.2 U64.9
N117386249: C53.1 R132.2 U16.11
N117386325: C53.2 R127.2 U16.12
N117386356: C51.1 U16.13
N117386392: C51.2 U16.14
N117386460: C59.1 R167.2 U16.8
N117386466: R162.1 U16.6
N117386498: R120.1 R128.1 U16.1
N117386536: C59.2 R166.2 U16.7
N117386581: R115.1 U16.16
N117386598: C56.1 R134.2 U16.10
N117386638: C56.2 R148.2 U16.9
N117386716: C57.1 R152.2 U17.11
N117386852: C57.2 R149.2 U17.12
N117386899: C55.1 R126.2 U17.13
N117386951: C55.2 R125.2 U17.14
N117387023: C62.1 R184.2 U17.8
N117387029: R176.1 U17.6
N117387061: R145.1 R150.1 U17.1
N117387099: C62.2 R183.2 U17.7
N117387144: R124.1 U17.16
N117387161: C60.1 R161.2 U17.10
N117387201: C60.2 R165.2 U17.9
N117387282: C72.1 R200.2 U21.11
N117387358: C72.2 R197.2 U21.12
N117387408: C68.1 R182.2 U21.13
N117387460: C68.2 R181.2 U21.14
N117387535: C85.1 R232.2 U21.8
N117387541: R230.1 U21.6
N117387573: R195.1 R199.1 U21.1
N117387611: C85.2 R231.2 U21.7
N117387659: R180.1 U21.16
N117387676: C79.1 R213.2 U21.10
N117387716: C79.2 R220.2 U21.9
N117391298: R438.2 U24.7
N117391560: R436.2 U19.7
N117392496: C96.1 D19.A U33.5(VOUT)
N117392540: C97.1 U33.4
N117392714: R156.2 U18.1
N117392721: R155.2 U18.2
N117395484: R189.2 R190.2 U23.18
N117395690: R188.2 U23.20
N117395722: R191.2 U23.15
N117395724: R235.2 R242.1 U23.3
N117395763: R237.2 U23.31
N117395797: R169.2 U23.12
N117395822: R168.2 U23.13
N117396221: R236.2 U23.30
N117396699: D28.A R382.2
N117397706: C162.1 U40.2
N117397841: C157.2 U40.14(VMID)
N117397843: C149.1 U40.5
N117397886: C149.2 U40.3
N117397940: R306.2 R307.1 U40.12
N117398055: C165.2 R334.1
N117398057: C166.2 R337.1
N117399431: C38.1 R43.1 S1.2
N117399829: C39.1 R44.2 S1.1(NC)
N117400024: D3.C R46.1
N117400223: R79.2 U12.1
N117400330: R82.2 U12.3
N117400348: R83.2 U12.4
N117400350: TP7.1(PIN1) U12.12
N117400364: TP24.1(PIN1) U12.8
N117400372: TP11.1(PIN1) U12.9
N117400380: TP8.1(PIN1) U12.10
N117400386: TP10.1(PIN1) U12.11
N117403125: Q8.3 R319.2 R320.2 U45.A3(\\E\N)
N117403218: R383.1 SW5.2
N117403229: R381.2 SW5.3
N117403272: R385.1 SW5.5
N117403287: R380.2 SW5.6(NO2)
N117403318: TP172.1(PIN1) U52.C3
N117403325: C163.1 Q8.1 R321.1 R339.2
N117403441: Q10.3 R375.2 R376.2
N117403643: R338.1 U49.5
N117404021: C173.1 R360.1 U39.27
N117404068: R479.2 U58.5
N117404089: R478.1 U58.6
N117404099: C306.1 U39.19
N117404161: R476.2 R477.2 U58.2
N117404173: C306.2 L12.1 U39.9 U39.10 U39.11 U39.12 U39.34
N117404204: L12.2 R360.2 R365.1
N117404484: C159.1 R317.2
N117417066: C78.1 U24.1
N117417617: C63.1 U19.1
N117424543: R102.2 U2.G11
N117426825: R114.1 U1.A3
N117433736: TP103.1(PIN1) U25.K5
N117434649: R216.2 U26.B2
N117439420: R129.2 R130.2 R434.2 U15.30
N117439422: R121.2 R122.2 R433.2 U15.29
N117439424: C49.1 R118.2 R430.2 U15.28
N117439483: R137.1 U15.1
N117439503: R138.1 U15.2
N117439523: R139.1 U15.3
N117439558: R140.1 U15.4
N117439590: R141.1 U15.5
N117439655: R142.1 U15.6
N117439684: R63.1 SW4.2
N117439704: R135.2 R136.2 U15.32
N117439710: R143.1 U15.7
N117439737: R67.1 SW4.4
N117439768: R144.1 U15.8
N117439790: R90.1 SW4.6
N117439833: R97.1 SW4.8
N117439837: R131.1 U15.9
N117439852: R123.1 U15.10
N117439873: R119.1 U15.11
N117439950: R116.1 U15.12
N117439995: R110.1 U15.13
N117440027: R101.1 U15.14
N117440047: R99.1 U15.15
N117440102: R95.1 U15.16
N117440157: R75.1 U15.17
N117440173: R74.1 U15.18
N117440199: R73.1 U15.19
N117440226: R72.1 U15.20
N117440257: R71.1 U15.21
N117440277: R70.1 U15.22
N117440294: R69.1 U15.23
N117440315: R68.1 U15.24
N117440815: R266.1 U30.13
N117440819: R265.1 U29.13
N117440823: R404.1 U9.13
N117441408: R465.2 R467.2 U31.13
N117441414: R39.1 U10.13
N117441435: R442.1 U27.13
N117446518: R289.2 R299.1 U36.4
N117446570: D29.C(CATHODE) R288.2 R298.1 U36.3
N117446967: C181.1 U47.A6
N117446993: C183.1 U47.A3
N117447048: R367.2 U47.A2
N117447064: R340.2 R475.2 U47.E1
N117447556: C164.1 D24.C D25.C U46.2
N117447734: TP166.1(PIN1) U51.C3
N117451840: R263.2 U35.14
N117451860: R267.2 U35.13
N117452169: R271.1 U35.39
N117456939: L10.1 U32.1 U32.9
N117457136: C122.2 R268.2 R269.1 U32.3
N117457322: R273.2 R277.2 U32.6
N117457326: C123.1 U32.4
N117457386: TP142.1(PIN1) U32.7
N117457835: D27.A R318.1
N117457859: R355.1 U44.2
N117457920: R356.1 U44.3
N117457977: R357.1 U44.4
N117458015: R358.1 U44.5
N117458076: D26.A R322.1
N117458080: R316.1 U44.12
N117458344: J8.55 TP177.1(PIN1)
N117462626: R5.2 R11.1 U6.C2
N117462672: D1.4(CATHODE3) R390.1
N117462674: D1.3 R388.1
N117462676: D1.1 R389.1
N117462986: Q13.1 R395.2 R396.1
N117462992: Q11.1 R391.2 R392.1
N117463000: Q12.1 R393.2 R394.1
N117463075: R1.2 R2.1 U67.C2
N117463350: R10.1 SW1.3 SW1.4
N117463581: R14.1 SW2.3 SW2.4
N117466193: R379.1 U56.1
N117466207: R12.1 U4.1
N117466246: R371.2 U56.2
N117466262: R4.2 U4.2
N117466578: R384.1 U57.1
N117466582: R13.1 U5.1
N117466611: R372.2 U57.2
N117466616: R3.2 U5.2
N117466869: C22.2 R18.2 R26.1 U7.4
N117466881: R17.2 U7.3
N117474140: C292.1 C302.1 L16.2 U28.9
N117474237: C180.1 U50.4
N117474317: R403.1 U60.4
N117474345: R402.1 U60.5
N117474374: R412.1 U60.1
N117474402: R411.1 U60.16
N117474428: C293.1 C303.1 L17.2 U28.4
N117474503: R410.2 U60.15
N117474505: R401.1 U60.6
N117474615: R409.2 U60.13
N117474617: R400.1 U60.8
N117475319: TP122.1(PIN1) U28.29
N117475358: TP114.1(PIN1) U28.32
N117475382: TP101.1(PIN1) U28.33
N117475402: TP100.1(PIN1) U28.34
N117475466: D17.A R219.1
N117475515: D16.A R226.1
N117475774: TP97.1(PIN1) U28.48
N117475802: TP123.1(PIN1) U28.52
N117475809: C135.1 R282.2 U28.14
N117475826: R284.1 U28.6
N117476127: R418.1 U62.7
N117476217: R416.1 U62.5
N117476285: R60.2 R64.2 U13.22
N117476287: R21.1 R38.2 U13.18
N117476313: R398.1 U62.2
N117476531: D5.A R112.2
N117476554: TP15.1(PIN1) U13.8
N117476682: R86.2 U14.1
N117476684: TP13.1(PIN1) U13.17
N117476744: R77.2 R78.1 R425.1 U14.2
N117477451: Q3.3 R172.2 R178.2
N117477453: Q4.3 R187.2 R194.2
N117477455: Q5.3 R198.2 R212.2
N117477457: D15.A R206.2
N117477459: D15.C(CATHODE) Q6.3 R221.2 R225.2
N117477506: D20.C R259.1
N117477781: J7.7 R301.1
N117477804: J7.9 R302.1
N117479041: R27.2 SW3.2
N117479043: R29.2 SW3.4
N117479045: R30.2 SW3.6
N117479047: R32.2 SW3.8

Pads without a net: J4 15 16; J8 35 37 41 43 44 46 47 48 49 53 59 61 65 66 67 68 70 71 73; J10 1 5 6; J11 A2 A3 A8 A10 A11 B2 B3 B8 B10 B11; J12 A2 A3 A8 A10 A11 B2 B3 B8 B10 B11; SW5 1 4; U2 A1 A2 A11 A12 AA1 AA2 AA4 AA9 AA11 AA12 AB1 AB2 AB11 AB12 B1 B12 K5 K8 N5 N8 P2 P4 P5 P8 P9 P11 R2 R3 R4 R9 R10 R11 T2 U2 U4 U9 U11 V2 V3 V4 V9 V10 V11 W3 W10 Y2 Y3 Y4 Y9 Y10 Y11; U3 1; U10 10 11 12; U14 5; U19 2; U24 2; U25 A1 A2 A7 A8 A9 A10 A11 A12 A13 A14 B1 B7 B8 B9 B10 B11 B12 B13 B14 C1 C3 C5 C7 C8 C9 C10 C11 C12 C13 C14 D1 D2 D3 D4 D12 D13 D14 E1 E2 E3 E5 E8 E9 E10 E12 E13 E14 F1 F2 F3 F10 F12 F13 F14 G1 G2 G3 G10 G12 G13 G14 H1 H2 H3 H12 H13 H14 J1 J2 J3 J12 J13 J14 K1 K2 K3 K6 K7 K10 K12 K13 K14 L1 L2 L3 L12 L13 L14 M1 M2 M3 M7 M8 M9 M10 M11 M12 M13 M14 N1 N3 N6 N7 N8 N9 N10 N11 N12 N13 N14 P1 P2 P7 P8 P9 P10 P11 P12 P13 P14; U28 40 41 43 44 45 46 53 54 55 57 58 59; U29 7 8 9 10 11 12; U34 1; U39 13 18 20 22 32; U51 D1 D2; U52 D1 D2; U53 1; U59 7 8 9 10 11 12; U60 7 9 12 14; U66 1; U68 1

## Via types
v1: diameter 0.457, hole 0.203, TOP to BOTTOM, 1658 vias
v2: diameter 0.406, hole 0.203, TOP to BOTTOM, 214 vias
v3: diameter 0.457, hole 0.206, TOP to BOTTOM, 111 vias
v4: diameter 0.356, hole 0.203, TOP to BOTTOM, 1 via

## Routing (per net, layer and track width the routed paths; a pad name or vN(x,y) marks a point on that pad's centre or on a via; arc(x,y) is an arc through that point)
AGND: length 2.7
  TOP w0.203: U23.34 47.79,40.88 v1(47.88,40.79)
  BOTTOM w0.381: v1(47.88,40.79) C254.1 48.01,39.88 48.01,39.12 48.01,39.12 R439.2
GND: length 558.6
  TOP w0.086: U25.N2 108.51,38.28 107.96,38.28 v2(107.7,38.54) 107.93,38.78 108.5,38.78 U25.N2
  TOP w0.203: U2.C1 82.16,55.38 v2(82.16,55.31) ; R66.2 v1(127.89,67.82) ; v2(98.56,57.16) U1.A17 ; U25.P4 110.26,38.53 U25.N5 U25.P6 ; v2(97.26,51.83) 97.23,51.81 U1.M15 97.23,50.83 v2(97.27,50.79) 97.23,50.75 U1.P15 ; U2.E1 81.19,56.17 v2(81.28,56.26) ; v2(97.26,52.87) 97.23,52.9 U1.H15 97.23,53.85 v2(97.26,53.88) 97.23,53.9 U1.F15 97.23,54.81 v2(97.26,54.83) 97.23,54.86 U1.D15 ; U1.C14 v2(96.23,55.83) U1.C12 ; U1.U17 98.53,48.54 v2(98.53,48.48) ; R50.2 v1(124.71,70.99) ; v2(89.99,57.23) 89.99,57.08 U1.A1 ; U1.U1 v2(89.85,48.39) ; R96.2 v1(127.76,65.28) ; v1(32.51,13.21) 32.3,13.42 U48.5 ; U2.K11 77.79,47.71 v2(77.5,48.01) ; R61.2 v1(114.93,68.39) ; R89.2 v1(127.89,66.55) ; U25.A6 v2(110.62,44.96) ; U25.C4 v2(110.24,43.05) ; R62.2 v1(127.89,69.09)
  TOP w0.254: R78.2 v1(40.77,67.43) ; D7.2 D9.2 v1(128.65,55.45) ; v1(93.54,70.99) 93.6,70.93 R59.2 ; J11.B12 11.73,6.27 J11.A1 v1(11.73,7.87) ; v2(74.36,46.51) 74.36,46.58 U2.T12 ; R35.2 75.31,74.42 v1(75.18,74.55) ; v1(109.6,37.47) 109.76,37.62 U25.P4 ; U1.R8 93.23,49.83 v2(93.19,49.79) 93.15,49.83 U1.R6 92.27,49.83 v2(92.23,49.79) 92.2,49.83 U1.R4 v2(91.23,49.83) U1.P3 v2(91.23,50.83) U1.M3 91.23,51.81 v2(91.21,51.83) 91.23,51.86 U1.K3 91.23,52.81 v2(91.21,52.83) 91.23,52.86 U1.H3 91.23,53.83 v2(91.21,53.86) 91.23,53.88 U1.F3 91.23,54.81 v2(91.21,54.83) 91.23,54.86 U1.D3 ; J8.63 v1(123.54,5.21) ; R321.2 v1(75.44,20.45) ; U13.24 41.3,68.6 v1(41.15,68.45) ; U28.35 13.8,39.74 v1(13.81,39.75) ; U2.J3 78.26,54.43 v2(78.26,54.51) ; v2(69.81,50.51) 69.81,50.43 U2.AB8 ; v2(81.27,50.79) 81.16,50.68 81.16,50.13 U2.E8 ; U51.B3 v1(27.49,12.83) ; v2(92.24,55.88) 92.28,55.83 U1.C6 93.19,55.83 v2(93.24,55.88) 93.28,55.83 U1.C8 ; U2.G8 80.21,49.78 v2(80.21,49.71) ; v2(75.66,48.11) 75.99,47.78 U2.N11 ; R83.1 v1(17.53,65.82) ; v2(76.31,49.71) 76.31,49.63 U2.N9 ; R8.2 v1(56.26,77.34) ; U2.W11 72.41,48.03 v2(72.41,48.11) ; U24.6 58.69,40.34 v1(58.55,40.2) ; v3(18.8,69.6) 18.78,69.58 U12.7 ; v2(78.26,46.51) 78.26,46.57 78.27,46.57 78.27,46.59 U2.J12 ; U2.E12 81.19,46.45 v2(81.28,46.36) ; v2(79.56,48.11) 79.56,48.18 U2.G10 ; U67.C1 87.88,83.31 v1(88.01,83.44) ; U51.D3 v1(28.29,12.83) ; U41.6 v1(124.33,21.21) ; v2(113.26,41.15) 113.14,41.03 U25.H10 ; GND15.1 v1(104.08,40.96) ; U2.C8 82.81,50.43 v2(82.81,50.51) ; v2(75.66,53.71) 75.66,53.78 U2.P3 ; U2.N2 75.66,55.23 v2(75.66,55.31) 75.66,55.38 U2.P1 ; v2(71.11,56.11) 71.11,56.03 U2.Y1 ; v2(80.21,52.91) 80.21,52.83 U2.G5 ; U2.V12 73.06,46.58 v2(73.06,46.51) ; U40.13 v1(104.27,21.27) ; U29.6 v1(112.72,34.16) ; C70.2 v1(48.91,48.26) ; J8.45 v1(128.04,5.21) ; R54.2 v1(87.76,71.06) ; U54.B1 14.99,9.27 15.24,9.53 v1(15.24,9.78) ; v2(111.51,42.04) 111.26,42.29 U25.E7 ; U30.6 v1(117.17,34.04) ; J8.51 v1(126.54,5.21) ; v2(69.81,48.11) 69.81,48.17 69.82,48.17 69.82,48.19 U2.AB10 ; v1(85.85,37.02) 85.85,36.32 84.84,36.32 ; J8.39 v1(129.54,5.21) ; v2(82.16,52.91) 82.16,52.98 U2.D4 ; U1.M8 93.7,51.37 v2(93.23,51.37) ; v2(69.81,52.11) 69.81,52.17 69.82,52.17 69.82,52.19 U2.AB5 ; v2(74.36,48.11) 74.36,48.18 U2.T10 ; v1(7.49,28.19) 7.3,28 U28.1 ; v2(79.96,56.26) 79.89,56.19 U2.G1 ; v2(75.66,46.51) 75.66,46.58 U2.P12 ; U2.V8 72.41,50.43 v2(72.41,50.51) ; U52.D3 v1(74.9,11.28) ; R82.1 v1(16.51,65.82) ; v1(88.52,21.08) U37.3 U37.8 v1(88.52,23.62) ; J12.B1 32.68,6.19 32.68,7 J12.A12 v1(32.59,7.87) ; v2(78.58,56.26) 78.59,56.25 U2.J1 ; v2(73.06,52.91) 73.06,52.83 U2.V5 ; U47.B4 U47.B3 U47.B2 ; U47.B4 U47.A4 v1(19.1,14.48) ; U47.B4 U47.B5 ; v1(4.19,35.43) 4.27,35.52 U28.51 ; R284.2 v1(11.81,23.37) ; R265.2 v1(111.38,27.81) ; U2.D9 82.16,49.63 v2(82.16,49.71) ; R302.2 v1(80.52,21.34) ; U2.D11 82.16,47.38 v2(82.16,47.31) 82.16,47.23 U2.C12 ; U6.C1 88.13,77.21 v1(88.27,77.34) ; v1(93.6,23.62) U38.8 U38.3 v1(93.6,21.08) ; v2(71.76,49.71) 71.76,49.63 U2.W9 ; U1.J6 v2(92.73,53.34) U1.G6 U1.F6 v2(93.22,54.33) U1.F8 v2(94.23,54.33) U1.F10 ; C12.2 v1(8.64,78.61) ; U40.4 v1(112.65,21.27) ; v2(73.71,54.51) 73.71,54.43 U2.T3 ; R33.2 v1(73.28,74.3) ; J12.B12 27.09,6.27 J12.A1 v1(27.09,7.87) ; v2(81.39,51.89) 81.19,52.1 U2.E5 ; v2(73.71,52.91) 73.71,52.83 U2.T5 ; v2(74.36,50.51) 74.36,50.43 U2.T8 ; v1(58.17,48.51) 58.02,48.66 U19.6 ; R39.2 95.38,72 C32.2 ; U2.K2 77.69,55.15 v2(77.69,55.28) ; v2(71.11,50.51) 71.11,50.43 U2.Y8 ; C45.2 C44.2 v1(81.03,67.06) ; v1(93.73,63.37) 93.6,63.5 93.6,66.33 93.85,66.59 Y1.2 v1(94.66,67.61) 94.87,67.82 C41.2 95.24,68.14 95.49,68.39 v1(95.76,68.39) 97.17,68.39 97.42,68.14 C42.2 97.98,67.26 v1(97.98,65.28) 97.69,64.99 Y1.4 96.86,63.08 94.74,60.96 v1(94.74,60.71) ; J8.33 v1(131.04,5.21) ; C163.2 v1(74.42,20.7) ; R377.2 v1(13.8,9.78) ; v2(93.23,51.37) 92.77,51.37 U1.M6 ; v2(93.23,51.37) U1.L7 ; v2(75.01,48.91) 75.01,48.83 U2.P10 ; v2(95.23,50.77) 95.17,50.83 U1.N10 U1.M10 95.21,51.33 v2(95.23,51.31) 95.26,51.33 U1.M12 ; R338.2 v1(69.85,18.16) ; v2(72.41,56.11) 72.41,56.03 U2.V1 ; J8.69 v1(122.04,5.21) ; U1.K9 v2(94.23,52.83) U1.H9 ; v2(75.66,52.91) 75.66,52.97 75.67,52.97 75.67,52.99 U2.N4 ; R307.2 v1(102.49,23.43) ; R21.2 v1(38.73,73.66) ; U2.W2 71.76,55.23 v2(71.76,55.31) ; J8.57 v1(125.04,5.21) ; U1.R10 v2(95.25,49.83) U1.R12 96.19,49.83 v2(96.23,49.79) 96.27,49.83 U1.R14 ; C112.2 85.6,30.99 v1(85.85,31.24) ; v1(85.85,34.42) R254.2 C95.2 ; U9.6 118.06,71.17 v1(118.11,71.12) ; R266.2 v1(115.82,27.81) ; R340.1 v1(23.75,16.76) ; D12.2 128.96,51 v1(128.65,51.31) ; v1(39.37,65.91) 39.5,65.78 U14.3 ; U28.25 v1(17.91,33.02) ; R311.2 v1(68.83,22.1) ; v1(92.39,70.99) 92.46,70.93 R58.2 ; U25.P6 110.76,37.72 v1(111.01,37.47) ; v2(71.76,52.91) 71.76,52.97 71.77,52.97 71.77,52.99 U2.W4 ; C135.2 v1(12.83,24) ; U2.Y12 71.12,46.59 71.12,46.57 71.11,46.57 v2(71.11,46.51) ; GND2.1 v1(66.9,15.6) ; U52.B3 74.73,10.09 v1(74.68,10.03) ; U2.K4 77.62,52.99 77.62,52.97 77.61,52.97 v2(77.61,52.91) ; U28.5 v1(9.3,28.19) ; C169.1 v1(70.87,18.42) ; GND13.1 v1(105.41,44.2) ; U2.A10 v2(84.33,48.51) ; U39.25 46.26,23.85 ; R229.2 v1(88.77,40.64) ; R7.2 v1(55.24,77.34) ; U2.D2 82.16,55.23 v2(82.16,55.31) ; U1.G12 95.73,53.42 v2(95.78,53.38) 95.78,53.37 95.73,53.32 U1.J12 ; U2.A3 v2(84.33,54.11) ; J8.1 v1(139.04,5.21) ; U2.Y5 71.12,52.19 71.12,52.17 71.11,52.17 v2(71.11,52.11) ; R36.2 v1(77.34,74.3) ; U44.6 v1(139.95,19.69) ; v2(79.56,53.71) 79.56,53.78 U2.G3 ; v2(82.81,52.11) 82.81,52.18 U2.C5 ; U22.3 v1(133.99,43.5) ; J8.18 v1(134.79,15.11) ; D11.2 129.66,51.74 v1(129.67,51.74) ; U13.23 v1(41.15,69.1) ; GND19.1 v1(105.41,36.58) ; U26.B1 v1(135.51,39.62) ; J8.7 v1(137.54,5.21) ; U28.15 v1(14.3,25.91) ; R114.2 v1(85.72,62.48) ; U45.E3 U45.D3 U45.C3 ; U28.47 v1(7.8,37.47) ; U2.K9 78.26,48.98 v2(78.26,48.91) 78.26,48.83 U2.J10 ; U27.6 v1(83.18,35.23) ; U31.6 v1(127.58,34.04) ; U21.3 v1(17.34,45.01) ; U43.6 v1(131.32,19.69) ; U15.26 113.56,63.73 v1(113.28,64.01) 113.51,64.23 U15.25 ; C17.2 v1(24.26,77.72) ; U25.K8 v2(111.76,39.5) ; C47.2 v1(88.01,64.26) ; U66.3 v1(78.74,82.54) ; J8.75 v1(120.54,5.21) ; R304.2 v1(83.44,23.37) ; v1(87.25,25.91) 86.87,26.29 R271.2 ; 87.88,36.32 v1(87.88,37.02) ; Q8.2 v1(72.26,20.46) ; C9.2 v1(12.07,78.23) ; v1(110.3,62.04) C49.2 ; R378.2 v1(19.81,10.54) ; D13.2 v1(128.65,49.86) ; U11.A2 v1(103.12,70.29) ; U25.J5 v2(110.74,40.53) ; v1(33.15,11.56) 33.02,11.43 C187.1 ; v1(30.61,9.72) 30.61,9.53 30.35,9.27 U55.B1 ; R111.2 v1(125.54,62.99) ; U25.G5 v2(109.73,41.53) ; R308.2 v1(103.5,23.43) ; C69.2 v1(47.1,48.01) ; v2(79.56,46.51) 79.56,46.57 79.57,46.57 79.57,46.59 U2.G12 ; TP95.1 v1(86.23,40.67) ; v2(74.02,56.26) 74.04,56.25 U2.T1 ; C199.2 v1(81.91,3.05) ; U28.13 v1(13.3,25.91) ; U2.AB3 69.81,54.43 v2(69.81,54.51) ; GND28.1 v1(17.14,8.64) ; v1(126.63,48.39) D14.2 ; v1(123.51,41.28) 123.83,41.59 U20.4 ; C148.2 v1(85.98,23.62) ; R301.2 v1(79.25,21.34) ; v1(46.74,69.6) U13.9 ; C198.2 v1(80.9,3.05) ; v2(96.2,54.79) 96.16,54.83 U1.E12 ; C48.2 v1(91.25,64.26) ; U28.10 11.8,27.93 v1(12.07,28.19) 12.3,27.96 U28.11 ; C180.2 v1(3.3,13.46) ; J11.B1 17.23,6.27 J11.A12 v1(17.23,7.87) ; C121.2 v1(84.2,27.43) ; U11.B1 v1(102.23,71.18) ; D6.2 v1(129.67,57.73) ; U10.6 v1(100.97,70.79) ; TP28.1 v1(15.7,60.25) ; Q10.2 v1(67.82,9.51) ; C36.2 v1(90.55,71.25) ; R53.2 v1(86.49,71.06)
  TOP w0.381: C88.2 47.12,38.83 v1(47.12,38.35) ; C28.2 v1(37.97,72.9) ; C25.2 v1(16.76,76.07) ; C27.1 v1(30.61,72.9) ; C167.2 v1(137.16,17.91) ; J4.34 v1(134.62,83.57) ; GND27.1 v1(113.79,15.88) ; C177.2 v1(13.02,13.59) ; TP40.1 v1(110.11,55.63) ; v1(85.47,78.68) C5.2 v1(86.74,79.55) ; v1(23.5,56.26) 23.55,56.31 24.09,56.31 R150.2 ; U3.3 6.67,78.98 v1(6.67,78.55) ; v1(80.64,10.41) U57.7 81.07,9.75 U57.3 81.36,8.38 81.89,8.38 U57.8 v1(82.55,8) ; C32.2 v1(94.68,71.12) ; C35.2 v1(94.68,70.1) ; v1(23.5,26.29) C124.2 U33.2 ; R199.2 v1(14.99,46.36) ; v1(27.94,61.09) C52.2 ; C157.1 v1(101.73,20.96) ; v1(77.98,17.02) R361.1 v1(79.25,17.91) ; U17.3 v1(25.78,54.67) ; SW1.1 v1(13.56,81.85) ; D28.C v1(64.77,0.76) ; U4.7 v1(4.06,81.28) ; C6.2 v1(33.02,80.26) ; C128.2 v1(7.49,24) ; C192.1 v1(72.9,10.03) ; C15.2 v1(28.19,77.22) ; C89.2 v1(48.39,38.1) ; R230.2 v1(19.43,40.13) ; U57.6 v1(78.74,8) ; 45.59,53.85 v1(45.59,52.53) ; U53.3 v1(6.1,8.75) ; C178.2 v1(115.85,13.59) ; SW2.2 v1(28.96,81.85) ; v1(82.93,17.02) C174.1 v1(81.66,17.91) ; C20.2 v1(3.49,74.33) ; C77.2 v1(140.34,46.1) ; C97.2 v1(25.53,32.26) ; C114.2 v1(113.41,27.56) ; C158.2 v1(137.1,20.45) ; C43.2 v1(26.42,66.29) ; TVS2.1 v1(107.7,14.48) ; U56.6 v1(2.16,8) ; GND16.1 v1(90.55,42.35) ; C61.2 v1(128.4,52.96) ; U56.5 v1(4.06,5.59) ; v1(8.25,24) 8.25,23.29 X1.4 ; C29.2 v1(62.23,72.01) ; R315.2 v1(120.27,19.81) ; C175.2 v1(25.15,14.99) ; 42.8,23.88 v1(42.8,24.64) ; C18.2 27.81,75.82 v1(27.81,75.5) U8.2 ; Y2.4 82.55,31.55 v1(82.55,32.26) ; Q5.2 v1(9.02,47.13) ; Q6.2 v1(9.02,44.34) ; C127.2 v1(35.69,25.02) ; C162.2 v1(115.19,19.81) ; R337.2 v1(112.89,18.22) ; J7.3 v1(76.71,23.62) ; C164.2 v1(28.7,17.91) ; v3(37.85,32.13) 38.73,33.02 TP3.1 ; U4.8 v1(5.97,78.87) ; C161.2 v1(101.85,19.81) ; TP12.1 v1(82.68,74.27) ; R299.2 v1(35.43,22.99) ; v1(9.52,78.49) 9.65,78.36 C13.2 ; J4.39 v1(142.24,74.04) ; C190.2 v1(116.41,10.29) ; C120.2 v1(117.86,27.56) ; J4.6 v1(99.06,83.57) ; J4.20 v1(116.84,83.57) ; J3.8 v1(69.85,74.55) ; U7.2 v1(7.62,74.3) ; TVS1.1 v1(109.22,14.48) ; C197.2 v1(8.76,6.22) ; U36.2 v1(28.83,24) ; v1(30.05,42.67) C80.2 ; C80.2 v1(29.21,43.43) ; C80.2 v1(30.05,44.32) ; C58.2 v1(24,54.48) ; C30.2 v1(14.48,70.99) ; R176.2 v1(27.94,49.72) ; C11.2 v1(7.62,78.61) ; Q3.2 v1(8.89,52.72) ; C134.2 v1(10.79,24) ; C125.1 v1(44.2,25.65) ; U56.7 v1(4.06,10.41) ; C34.2 v1(105.85,69.98) ; J6.11 v1(142.62,47.24) ; D29.A v1(25.53,21.84) ; R273.1 v1(141.6,28) ; U4.5 v1(4.06,76.45) ; GND7.1 v1(119.7,52.01) ; GND20.1 v1(98.04,32.64) ; v1(80.64,81.28) U5.7 81.07,80.62 U5.3 81.36,79.25 81.89,79.25 U5.8 v1(82.55,78.87) ; J6.13 v1(130.3,61.84) ; D10.2 v1(125.67,53.98) GND6.1 ; J6.12 v1(142.62,62.74) ; Q9.2 v1(126.1,21.21) ; C176.2 v1(25.15,13.97) ; R26.2 v1(12.45,73.28) ; GND1.1 v1(30.86,77.22) ; v1(49.78,38.04) 49.66,38.16 C90.2 ; TVS3.1 v1(11.94,10.92) ; R334.2 v1(104.03,18.22) ; C96.2 v1(23.46,32.26) ; U34.3 v1(73.29,28.07) ; J4.9 v1(104.14,74.17) ; C63.2 v1(52.45,51.44) ; R128.2 v1(41.15,59.56) ; C196.2 v1(8.76,7.24) ; U46.3 v1(24.13,17.4) ; C21.2 v1(5.33,73.53) ; C38.2 v1(30.61,70.36) ; C117.2 v1(116.84,27.56) ; U5.6 v1(78.74,78.87) ; R272.2 v1(139.2,28) ; C182.2 v1(18.54,11.81) ; C159.2 v1(40.89,20.8) ; C39.2 v1(37.97,70.49) ; U57.5 v1(80.64,5.59) ; 129.54,81.34 v1(129.54,83.57) ; v1(103.12,70.29) 103.43,69.98 C33.2 ; GND26.1 v1(103.12,15.88) ; C54.2 v1(41.66,57.79) ; 41.78,23.88 v1(41.78,24.64) ; R2.2 88,83.45 v1(88.01,83.44) ; R11.2 88.26,77.35 v1(88.27,77.34) ; J3.7 v1(69.85,83.19) ; Q4.2 v1(8.89,49.92) ; U4.6 v1(2.16,78.87) ; C185.2 v1(115.85,12.57) ; GND25.1 v1(13.72,23.37) ; 4.06,21.77 4.06,22.61 v1(4.19,22.73) ; TP75.1 v1(60.71,48.13) ; GND24.1 v1(100.08,25.02) ; J1.6 J1.5 ; C91.2 v1(50.8,38.04) ; X1.2 v1(10.12,20.19) ; J7.5 v1(77.98,23.62) ; v1(84.2,79.12) C8.2 C14.2 v1(84.2,76.58) ; GND12.1 v1(88.84,43.88) ; C7.2 v1(33.02,78.99) ; C113.2 v1(112.39,27.56) ; GND23.1 v1(114.55,25.53) ; C50.2 v1(44.83,62.74) ; SW1.2 v1(15.88,81.85) ; C171.2 v1(107.57,16) ; GND22.1 v1(104.77,25.78) ; GND4.1 v1(125.16,56.45) ; C191.2 v1(144.15,11.3) ; GND17.1 v1(123.51,41.28) ; U5.5 v1(80.64,76.33) ; R309.1 v1(42.29,21.34) ; C31.2 v1(48.51,70.49) ; U56.8 v1(5.97,8) ; C1.2 v1(84.2,83.31) ; J4.25 v1(124.46,74.1) ; C179.2 v1(143.76,13.59) ; U16.3 v1(43.43,57.97) ; C92.2 v1(52.07,38.35) ; Y2.2 v1(84.24,28.96) ; R367.1 v1(20.7,11.94) ; C24.2 v1(15.75,76.07) ; C37.2 v1(124.08,69.98) ; C65.2 v1(52.45,50.42) ; J4.14 v1(109.22,83.54) ; v1(10.52,12.6) U50.2 ; GND11.1 v1(126.63,48.39) ; C78.2 v1(61.72,45.85) ; v1(4.1,12.45) C188.2 ; C184.2 v1(13.02,12.57) ; C10.2 v1(5.91,77.85) ; D2.3 v1(34.29,77.98) ; C172.1 v1(109.35,16) ; C66.2 v1(54.93,50.42) ; C189.2 v1(13.08,11.56) ; C4.2 v1(10.29,82.3) ; C186.2 v1(143.76,12.57) ; C46.2 v1(42.29,65.28) ; v1(45.47,38.23) C87.1 ; C16.2 v1(86.87,77.8) ; C40.2 v1(124.46,68.96) ; C23.2 v1(14.22,76.45) ; R294.2 v1(25.89,24.15) ; R298.2 v1(26.67,22.99) ; v1(44.58,19.69) 43.94,19.69 C160.2 ; v1(19.43,51.44) C64.2 ; R269.2 v1(137.03,26.54) ; J6.10 v1(130.3,47.24) ; 19.69,12.45 v1(19.69,11.68) ; SW2.1 v1(22.1,81.85) ; R310.2 v1(135.38,22.1) ; Q1.2 v1(36.83,62.93) ; C195.2 v1(76.2,7.37) ; J6.6 v1(129.67,51.74)
  TOP w0.508: J13.B12 v1(42.72,7.62) ; J13.A12 v1(48.22,7.49)
  BOTTOM w0.203: U59.6 130.61,70.81 v1(130.68,70.74) ; R457.2 R456.2 R455.2 R454.2 ; U60.11 58.98,69.78 v1(59.18,69.98) 58.98,70.18 U60.10 ; U63.10 63.05,64.19 v1(63.25,64.39) 63.45,64.19 U63.11 ; R454.2 v3(94.49,32.64) ; R454.2 R453.2 R452.2 v1(96.52,32.64) ; v2(92.23,49.79) 92.34,49.79 92.71,50.17 C137.2 ; C211.2 77.13,48.37 v2(77.5,48.01)
  BOTTOM w0.254: C204.2 73.67,56.61 v2(74.02,56.26) 74.53,56.77 C207.2 ; v2(91.23,49.83) 91.17,49.89 C139.2 ; C144.2 94.22,54.34 v2(94.23,54.33) 94.24,54.34 C155.2 ; C144.2 93.23,54.34 v2(93.22,54.33) ; C144.2 93.73,53.84 93.91,53.66 C104.2 ; R404.2 115.56,73.03 v1(115.38,73.22) ; C101.2 95.95,55.83 v2(96.23,55.83) 96.23,56.43 C102.2 ; v2(84.33,54.11) 84.21,53.99 C214.2 ; v2(95.25,49.83) 95.17,49.91 C129.2 ; C260.2 109.49,37.58 v1(109.6,37.47) ; v2(75.66,52.91) 75.33,52.58 C210.2 ; R424.2 R423.2 R422.2 R421.2 68.64,65.91 v1(68.71,65.98) ; v2(95.78,53.38) 95.78,53.41 95.86,53.5 C145.2 95.83,53.86 95.83,53.86 C107.2 ; R442.2 v1(76.96,36.58) ; Q12.2 v1(74.54,75.69) ; v2(97.26,53.88) 97.63,54.24 C119.2 ; C106.2 95.25,51.32 v2(95.23,51.31) 95.72,51.31 C131.2 ; v2(80.21,52.91) 80.21,52.79 R208.1 ; v2(93.22,54.33) 93.16,54.4 C152.2 ; v2(93.22,54.33) 93.22,53.93 C111.2 ; R207.1 77.6,52.92 v2(77.61,52.91) ; 93.22,51.38 93.26,51.42 C110.2 ; 93.22,51.38 v2(93.23,51.37) ; 93.22,51.38 C115.2 ; C218.2 82.21,55.36 v2(82.16,55.31) ; R204.2 89.92,54.22 90.04,54.1 90.04,53.6 90.17,53.47 C151.2 90.82,53.47 v2(91.21,53.86) ; v2(71.11,46.51) 71.23,46.39 C222.2 ; R396.2 v1(72.14,74.94) ; v2(82.16,47.31) 82.34,47.13 C216.2 ; R411.2 R412.2 55.35,66.71 v1(54.73,66.71) ; C130.2 97.26,54.57 v2(97.26,54.83) ; v2(75.66,46.51) 75.81,46.36 C212.2 ; C256.2 111.87,39.38 v2(111.76,39.5) ; C136.2 90.57,50.68 C140.2 91.19,50.79 v2(91.23,50.83) ; v2(111.51,42.04) 111.39,41.92 C251.2 ; v2(81.27,50.79) 81.18,50.69 81.18,50.19 C217.2 ; v2(69.81,54.51) 69.84,54.53 C219.2 ; v2(71.11,50.51) 71.01,50.61 C220.2 ; C221.2 81.2,52.53 81.2,52.08 v2(81.39,51.89) ; C213.2 74.41,50.56 v2(74.36,50.51) ; v1(94.04,42.55) 93.93,42.66 C109.2 ; U65.6 v1(20.96,31.5) ; R403.2 v1(55.37,74.04) ; v2(91.21,52.83) 91.21,52.96 91.58,53.33 C138.2 ; v1(77.47,75.69) 77.47,76.89 Q11.2 ; v2(79.56,53.71) 79.74,53.89 C205.2 ; v1(49.15,70.49) 49.01,70.62 U62.4 ; C259.2 110.88,37.59 v1(111.01,37.47) ; C146.2 96.88,52.32 97.26,51.94 v2(97.26,51.83) ; U64.3 v1(34.04,33.47) ; v2(73.06,49.71) 73.14,49.63 C209.2 ; Q13.2 v1(71.74,76.2) ; C203.2 81.42,56.12 v2(81.28,56.26) ; C116.2 95.21,50.79 v2(95.23,50.77) ; v2(97.26,52.87) 97.26,52.79 97.61,52.44 C118.2 ; C132.2 98.54,48.47 v2(98.53,48.48) ; R432.2 v1(59.31,60.45) ; C105.2 95.33,42.66 95.44,42.55 v3(95.5,42.55) ; v2(106.93,42.8) 106.79,42.94 C247.2 C244.2 ; v2(89.99,57.23) 90.31,56.91 C133.2 ; R397.2 v1(49.66,73.91) ; R392.2 v1(77.98,74.94) ; v2(110.24,43.05) 110.22,43.07 C245.2 ; R417.2 v1(48.26,65.09) ; C208.2 84.21,48.63 v2(84.33,48.51) ; v2(75.66,48.11) 75.62,48.06 R201.2 ; U61.4 v1(50.56,69.47) ; C262.2 v1(91.44,37.66) ; R394.2 v1(75.82,74.3) ; v2(93.24,55.88) 92.96,55.88 C153.2 ; R399.2 v1(46.99,74.55)
  BOTTOM w0.381: C313.2 19.05,14.53 v1(19.1,14.48) ; R463.2 v1(33.27,30.23) ; C312.1 31.88,15.62 v3(31.5,15.24) ; C267.2 v1(76.71,35.56) ; C249.2 v1(60.2,43.37) 60.32,43.5 C243.2 ; C228.2 v1(53.59,70.49) ; v1(4.19,35.43) 4.32,35.31 C266.2 ; 114.05,64.26 113.54,64.26 v1(113.28,64.01) ; C292.2 12.19,28.07 v1(12.07,28.19) ; C305.2 v1(107.57,23.24) ; C223.2 v1(53.97,73.91) ; v1(69.98,16) 70.26,15.72 C314.2 ; C310.2 v1(131.06,19.05) ; C315.2 32.48,13.24 v1(32.51,13.21) ; 61.72,59.44 v1(61.72,58.61) ; R473.1 46.36,20.07 45.97,19.69 R474.2 v1(44.58,19.69) ; C297.2 v1(22.86,25.91) ; C261.2 v1(13.81,35.81) ; C273.2 v1(6.35,32) ; C258.2 v1(10.29,39.75) ; C264.2 v1(8.89,36.45) ; C252.2 113.35,41.24 v2(113.26,41.15) ; U68.3 131.06,48.47 C318.2 v1(129.67,49.91) ; C293.2 v1(7.49,28.19) ; v2(81.28,46.36) 81.15,46.22 C201.2 ; 63.75,59.44 v1(63.75,58.61) ; v1(85.85,34.42) 85.89,34.38 C271.2 ; C224.2 v1(111.7,72.52) ; C275.2 v1(85.85,31.24) ; GND14.1 v1(72.75,35.89) ; C240.2 17.52,44.83 v1(17.34,45.01) ; C302.2 v1(12.16,25.59) ; C229.2 41.16,69.09 v1(41.15,69.1) ; R441.2 v1(33.4,36.7) ; C288.2 v1(127.13,27.56) ; C287.2 v1(13.84,28.32) ; v2(75.66,55.31) 75.73,55.24 C206.2 ; C215.2 71.13,56.12 v2(71.11,56.11) ; C231.2 v1(53.59,68.45) ; C272.2 v1(32.26,33.66) ; C301.2 v1(87.25,25.91) ; C263.2 v1(15.75,36.96) ; R439.1 49.56,38.99 C257.2 49.82,38.07 v1(49.78,38.04) ; 122.68,20.57 v1(123.7,20.57) ; C316.2 v1(8.51,11.05) ; C303.2 v1(7.53,25.59) ; C230.2 v1(53.59,69.47) ; C237.2 v1(117.41,51.05) ; 62.74,59.44 v1(62.74,58.61) ; C300.2 v1(19.05,25.91) ; v1(3.68,18.16) 3.68,18.67 C311.2 ; C286.2 v1(73.02,30.23) ; C108.2 94.61,52.46 v2(94.23,52.83) ; C227.2 v1(53.59,71.5) ; R426.2 v1(39.37,65.91) ; C202.2 73.03,46.48 v2(73.06,46.51) ; C298.2 v1(21.84,25.91) ; C284.2 v1(37.34,28.83) ; 122.68,21.84 v1(123.7,21.84) ; C289.2 v1(126.11,27.56) ; 17.27,30.48 v1(18.03,30.48) ; C269.2 v1(76.71,34.54) ; 64.77,59.44 v1(64.77,58.61) ; C304.2 v1(44.7,24.38) ; v1(5.08,27.31) C290.2 ; C281.2 C280.2 ; C255.2 v2(107.7,39.5) ; C268.2 v1(8.76,35.43) ; C309.2 v1(131.06,20.32) ; C299.2 v1(20.07,25.91) ; C226.2 v1(111.7,71.5) ; C225.2 v1(41.15,72.1) ; C317.2 v1(51.82,8.13) ; C238.2 v1(117.6,50.04)
  vias: v1(0.76,85.22) v1(0.76,82.68) v1(0.76,80.14) v1(0.76,77.6) v1(0.76,75.06) v1(0.76,72.52) v1(0.76,69.98) v1(0.76,67.44) v1(0.76,64.9) v1(0.76,62.36) v1(0.76,59.82) v1(0.76,57.28) v1(0.76,54.74) v1(0.76,52.2) v1(0.76,49.66) v1(0.76,47.12) v1(0.76,44.58) v1(0.76,42.04) v1(0.76,39.5) v1(0.76,36.96) v1(0.76,34.42) v1(0.76,31.88) v1(0.76,29.34) v1(0.76,26.8) v1(0.76,24.26) v1(0.76,21.72) v1(0.76,19.18) v1(0.76,16.64) v1(0.76,14.1) v1(0.76,11.56) v1(0.76,9.02) v1(0.76,6.48) v1(0.76,3.94) v1(0.76,1.4) v1(1.4,85.73) v1(1.4,0.76) v1(3.94,85.73) v1(6.48,85.73) v1(6.48,0.76) v1(9.02,85.73) v1(9.02,0.76) v1(11.56,85.73) v1(11.56,0.76) v1(14.1,85.73) v1(14.1,0.76) v1(14.48,53.47) v1(14.48,52.07) v1(14.73,49.28) v1(14.73,48.39) v1(16.64,85.73) v1(16.64,0.76) v1(19.18,85.73) v1(19.18,23.75) v1(21.72,85.73) v1(21.72,0.76) v1(24.26,85.73) v1(24.26,0.76) v1(26.8,85.73) v1(26.8,0.76) v1(29.34,85.73) v1(29.34,0.76) v1(31.88,85.73) v1(31.88,0.76) v1(34.42,85.73) v1(36.96,85.73) v1(36.96,0.76) v1(39.37,44.64) v1(39.5,85.73) v1(39.5,0.76) v1(39.88,44.2) v1(40.39,45.59) v1(40.39,44.64) v1(40.39,42.8) v1(40.89,44.2) v1(41.4,44.64) v1(42.04,85.73) v1(42.04,0.76) v1(44.58,85.73) v1(44.58,0.76) v1(47.12,85.73) v1(47.12,0.76) v1(47.75,18.54) v1(48.64,18.92) v1(49.66,85.73) v1(49.66,18.92) v1(49.66,0.76) v1(52.2,85.73) v1(52.2,0.76) v1(52.32,2.92) v1(54.74,85.73) v1(54.74,0.76) v1(55.5,44.7) v1(55.5,44.07) v1(56.26,45.85) v1(56.26,44.7) v1(56.26,44.07) v1(56.26,43.31) v1(57.28,85.73) v1(57.28,0.76) v1(59.82,85.73) v1(59.82,0.76) v1(62.36,85.73) v1(62.36,0.76) v1(62.61,23.11) v1(63.63,23.11) v1(64.52,24.38) v1(64.52,23.5) v1(64.9,85.73) v1(65.66,0.76) v1(67.44,85.73) v1(67.44,0.76) v1(69.98,85.73) v1(71.75,0.76) v1(71.88,60.71) v1(72.52,85.73) v1(73.91,60.71) v1(74.17,62.87) v1(75.06,85.73) v1(75.06,0.76) v1(76.07,62.36) v1(77.6,85.73) v1(77.6,0.76) v1(80.14,85.73) v1(80.14,0.76) v1(82.68,85.73) v1(82.68,0.76) v1(84.58,50.17) v1(84.96,51.88) v1(85.22,85.73) v1(85.72,49.72) v1(87.76,85.73) v1(90.3,85.73) v1(92.08,76.33) v1(92.46,83.57) v1(92.46,81.79) v1(92.58,75.82) v1(92.84,85.73) v1(95.38,85.73) v1(97.92,85.73) v1(100.46,85.73) v1(103,85.73) v1(103.12,0.76) v1(105.54,85.73) v1(108.08,85.73) v1(110.62,85.73) v1(113.16,85.73) v1(113.54,0.76) v1(115.7,85.73) v1(116.08,0.76) v1(118.24,85.73) v1(118.62,0.76) v1(120.78,85.73) v1(121.16,0.76) v1(123.32,85.73) v1(123.7,0.76) v1(125.86,85.73) v1(126.24,0.76) v1(128.4,85.73) v1(128.78,0.76) v1(130.94,85.73) v1(131.32,0.76) v1(131.83,33.15) v1(132.72,33.15) v1(133.48,85.73) v1(133.6,33.15) v1(133.86,0.76) v1(134.37,37.08) v1(134.49,41.15) v1(134.49,33.15) v1(135.26,38.23) v1(135.38,42.8) v1(136.02,85.73) v1(136.4,0.76) v1(138.56,85.73) v1(138.94,0.76) v1(139.7,32.51) v1(140.59,32.51) v1(141.1,85.73) v1(142.11,31.88) v1(143.38,32.26) v1(143.64,85.73) v1(144.02,0.76) v1(144.65,85.09) v1(144.65,82.55) v1(144.65,80.01) v1(144.65,77.47) v1(144.65,74.93) v1(144.65,72.39) v1(144.65,69.85) v1(144.65,67.31) v1(144.65,64.77) v1(144.65,62.23) v1(144.65,59.69) v1(144.65,57.15) v1(144.65,54.61) v1(144.65,52.07) v1(144.65,49.53) v1(144.65,46.99) v1(144.65,44.45) v1(144.65,41.91) v1(144.65,39.37) v1(144.65,36.83) v1(144.65,34.29) v1(144.65,31.75) v1(144.65,24.13) v1(144.65,21.59) v1(144.65,19.05) v1(144.65,16.51) v1(144.65,13.97) v1(144.65,8.89) v1(144.65,6.35) v1(144.65,3.81) v1(144.65,1.27) v3(4.62,64.41) v3(4.72,61.77) v3(5.84,63.12) v3(6.88,64.39) v3(6.88,61.85) v3(15.24,52.58) v3(15.24,51.56) v3(16.26,70.87) v3(16.26,69.6) v3(16.26,52.58) v3(16.26,51.56) v3(17.53,70.87) v3(17.53,69.6) v3(18.8,70.87) v3(19.05,46.36) v3(19.05,45.34) v3(19.05,44.32) v3(20.07,46.36) v3(20.07,45.34) v3(20.07,44.32) v3(21.08,46.36) v3(21.08,45.34) v3(21.08,44.32) v3(27.56,56.01) v3(27.56,54.99) v3(27.56,53.98) v3(28.57,56.01) v3(28.57,54.99) v3(28.57,53.98) v3(29.59,56.01) v3(29.59,54.99) v3(29.59,53.98) v3(35.81,34.16) v3(35.81,33.15) v3(35.81,32.13) v3(36.83,34.16) v3(36.83,33.15) v3(36.83,32.13) v3(37.85,34.16) v3(37.85,33.15) v3(43.05,70.74) v3(43.05,69.85) v3(43.05,68.96) v3(43.94,70.74) v3(43.94,69.85) v3(43.94,68.96) v3(44.83,70.74) v3(44.83,69.85) v3(44.83,68.96) v3(45.21,59.31) v3(45.21,58.29) v3(45.21,57.28) v3(46.23,59.31) v3(46.23,58.29) v3(46.23,57.28) v3(46.86,45.09) v3(46.86,43.56) v3(47.24,59.31) v3(47.24,58.29) v3(47.24,57.28) v3(47.5,45.09) v3(47.5,43.56) v3(48.39,45.59) v3(48.39,44.96) v3(48.39,42.55) v3(49.15,44.32) v3(49.15,42.8) v3(49.78,44.32) v3(49.78,42.8) v3(71.25,13.84) v3(79.88,58.08) v3(85.6,48.9) v3(86.23,51.05) v3(86.74,49.02) v3(87.86,54.33) v3(90.04,30.35) v3(90.04,29.34) v3(90.04,28.45) v3(91.06,30.35) v3(91.06,29.34) v3(91.06,28.45) v3(92.08,30.35) v3(92.08,29.34) v3(92.08,28.45) v3(116.71,62.48) v3(120.14,47.37) v3(120.14,46.1) v3(120.14,44.83) v3(121.92,47.37) v3(121.92,46.1) v3(121.92,44.83) v3(123.44,47.37) v3(123.44,46.1) v3(123.44,44.83)
